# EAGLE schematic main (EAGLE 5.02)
CLASS: 5HNc; CREATE_DATE: 15.07.08; EDIT_DATE: 10.02.09; LAST_EDIT: 10.02; TITLE: xMedia - Connector; USERNAME: BWA; YEAR: 2009

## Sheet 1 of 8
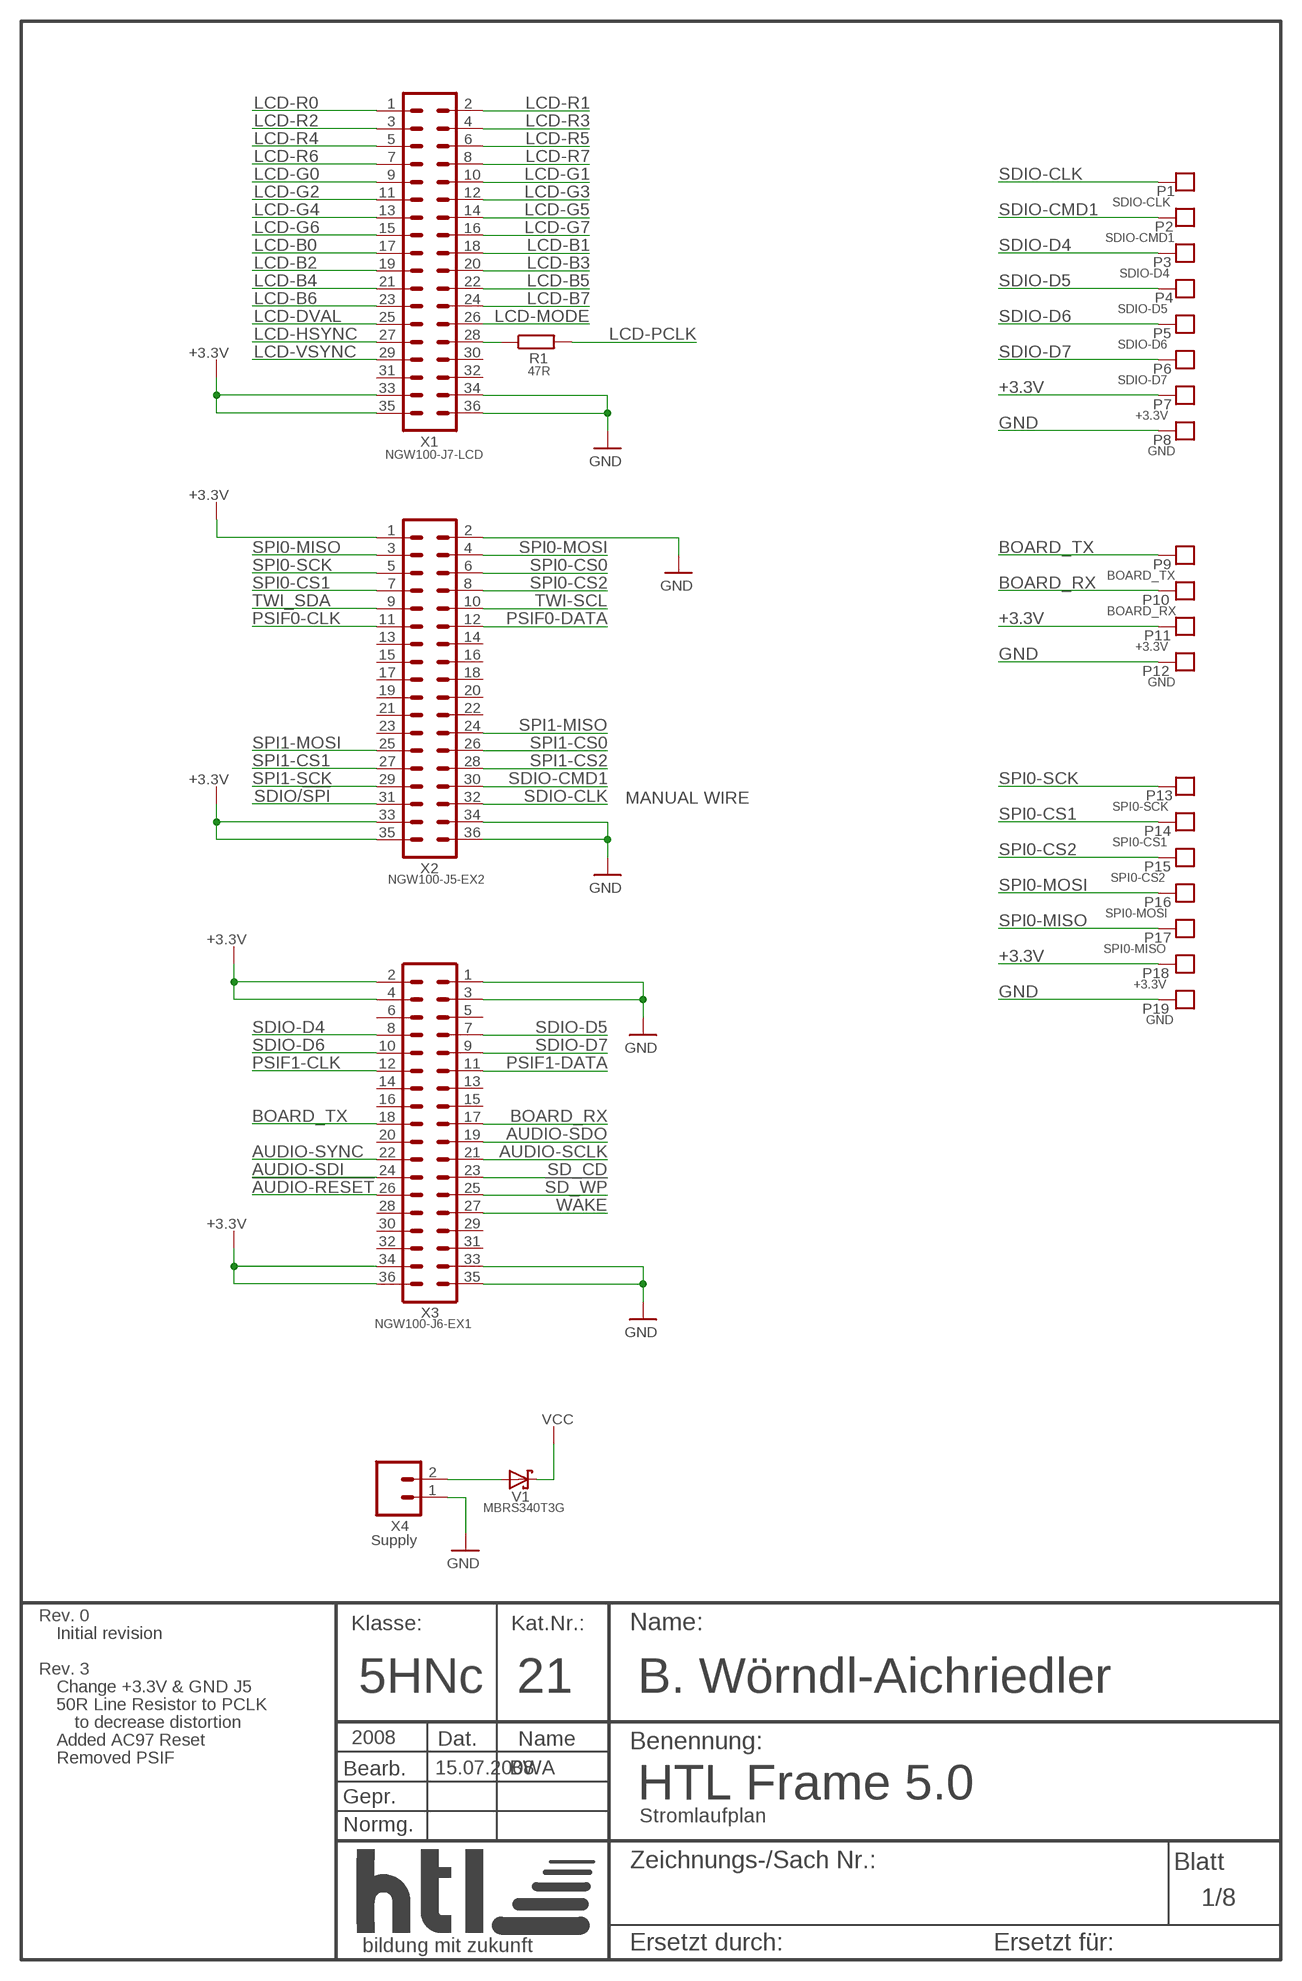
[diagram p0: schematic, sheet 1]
FRAME1 (HTL-FRAME-A4): CAT_NO: 21; CLASS: 5HNc; LAST_EDIT: 15.07.2008; SHORTNAME: BWA; SUBTITLE: Stromlaufplan; TITLE: HTL Frame 5.0; USERNAME: B. Wörndl-Aichriedler; YEAR: 2008

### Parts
P1  SDIO-CLK  TPB1,27  [B1,27]
P2  SDIO-CMD1  TPB1,27  [B1,27]
P3  SDIO-D4  TPB1,27  [B1,27]
P4  SDIO-D5  TPB1,27  [B1,27]
P5  SDIO-D6  TPB1,27  [B1,27]
P6  SDIO-D7  TPB1,27  [B1,27]
P7  +3.3V  TPB1,27  [B1,27]
P8  GND  TPB1,27  [B1,27]
P9  BOARD_TX  TPB1,27  [B1,27]
P10  BOARD_RX  TPB1,27  [B1,27]
P11  +3.3V  TPB1,27  [B1,27]
P12  GND  TPB1,27  [B1,27]
P13  SPI0-SCK  TPB1,27  [B1,27]
P14  SPI0-CS1  TPB1,27  [B1,27]
P15  SPI0-CS2  TPB1,27  [B1,27]
P16  SPI0-MOSI  TPB1,27  [B1,27]
P17  SPI0-MISO  TPB1,27  [B1,27]
P18  +3.3V  TPB1,27  [B1,27]
P19  GND  TPB1,27  [B1,27]
R1  47R  R-EU_R0805  [R0805]
V1  MBRS340T3G  SCHOTTKY-DIODESMC  [SMC]
X1  NGW100-J7-LCD  MA18-2WH  [MA18-2]
X2  NGW100-J5-EX2  MA18-2WH  [MA18-2]
X3  NGW100-J6-EX1  MA18-2WH  [MA18-2]
X4  Supply  M02  [02P]

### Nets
!AUDIO-RESET: X3.26 ; also sheet 6
!SD_WP: X3.25 ; also sheet 4
+3.3V: P7.PP(TP) P11.PP(TP) P18.PP(TP) X1.33 X1.35 X2.1 X2.33 X2.35 X3.2 X3.4 X3.34 X3.36 ; also sheet 2,3,4,5,6,7,8
AUDIO-SCLK: X3.21 ; also sheet 6
AUDIO-SDI: X3.24 ; also sheet 6
AUDIO-SDO: X3.19 ; also sheet 6
AUDIO-SYNC: X3.22 ; also sheet 6
BOARD_RX: P10.PP(TP) X3.17 ; also sheet 7
BOARD_TX: P9.PP(TP) X3.18 ; also sheet 7
GND: P8.PP(TP) P12.PP(TP) P19.PP(TP) X1.34 X1.36 X2.2 X2.34 X2.36 X3.1 X3.3 X3.33 X3.35 X4.1 ; also sheet 2,3,4,5,6,7,8
LCD-B0: X1.17 ; also sheet 2,3
LCD-B1: X1.18 ; also sheet 2,3
LCD-B2: X1.19 ; also sheet 2,3
LCD-B3: X1.20 ; also sheet 2,3
LCD-B4: X1.21 ; also sheet 2,3
LCD-B5: X1.22 ; also sheet 2,3
LCD-B6: X1.23 ; also sheet 2,3
LCD-B7: X1.24 ; also sheet 2,3
LCD-DVAL: X1.25 ; also sheet 3
LCD-G0: X1.9 ; also sheet 2,3
LCD-G1: X1.10 ; also sheet 2,3
LCD-G2: X1.11 ; also sheet 2,3
LCD-G3: X1.12 ; also sheet 2,3
LCD-G4: X1.13 ; also sheet 2,3
LCD-G5: X1.14 ; also sheet 2,3
LCD-G6: X1.15 ; also sheet 2,3
LCD-G7: X1.16 ; also sheet 2,3
LCD-HSYNC: X1.27 ; also sheet 2,3
LCD-MODE: X1.26
LCD-PCLK: R1.2 ; also sheet 2,3
LCD-R0: X1.1 ; also sheet 2,3
LCD-R1: X1.2 ; also sheet 2,3
LCD-R2: X1.3 ; also sheet 2,3
LCD-R3: X1.4 ; also sheet 2,3
LCD-R4: X1.5 ; also sheet 2,3
LCD-R5: X1.6 ; also sheet 2,3
LCD-R6: X1.7 ; also sheet 2,3
LCD-R7: X1.8 ; also sheet 2,3
LCD-VSYNC: X1.29 ; also sheet 2,3
N$15: V1.A X4.2
N$75: R1.1 X1.28
PSIF0-CLK: X2.11
PSIF0-DATA: X2.12
PSIF1-CLK: X3.12
PSIF1-DATA: X3.11
SD_CD: X3.23 ; also sheet 4
SDIO-CLK: P1.PP(TP) X2.32 ; also sheet 5
SDIO-CMD1: P2.PP(TP) X2.30 ; also sheet 5
SDIO-D4: P3.PP(TP) X3.8 ; also sheet 5
SDIO-D5: P4.PP(TP) X3.7 ; also sheet 5
SDIO-D6: P5.PP(TP) X3.10 ; also sheet 5
SDIO-D7: P6.PP(TP) X3.9 ; also sheet 5
SDIO/!SPI!: X2.31 ; also sheet 5
SPI0-CS0: X2.6
SPI0-CS1: P14.PP(TP) X2.7 ; also sheet 4
SPI0-CS2: P15.PP(TP) X2.8 ; also sheet 4
SPI0-MISO: P17.PP(TP) X2.3 ; also sheet 4
SPI0-MOSI: P16.PP(TP) X2.4 ; also sheet 4
SPI0-SCK: P13.PP(TP) X2.5 ; also sheet 4
SPI1-CS0: X2.26 ; also sheet 4
SPI1-CS1: X2.27
SPI1-CS2: X2.28
SPI1-MISO: X2.24 ; also sheet 4
SPI1-MOSI: X2.25 ; also sheet 4
SPI1-SCK: X2.29 ; also sheet 4
TWI-SCL: X2.10
TWI_SDA: X2.9
VCC: V1.C ; also sheet 2,6
WAKE: X3.27 ; also sheet 7
Unconnected: X1.30 X1.31 X1.32 X2.13 X2.14 X2.15 X2.16 X2.17 X2.18 X2.19 X2.20 X2.21 X2.22 X2.23 X3.5 X3.6 X3.13 X3.14 X3.15 X3.16 X3.20 X3.28 X3.29 X3.30 X3.31 X3.32

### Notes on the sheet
- MANUAL WIRE
- Rev. 0
- Initial revision
- Rev. 3
- Change +3.3V & GND J5
- 50R Line Resistor to PCLK
- to decrease distortion
- Added AC97 Reset
- Removed PSIF

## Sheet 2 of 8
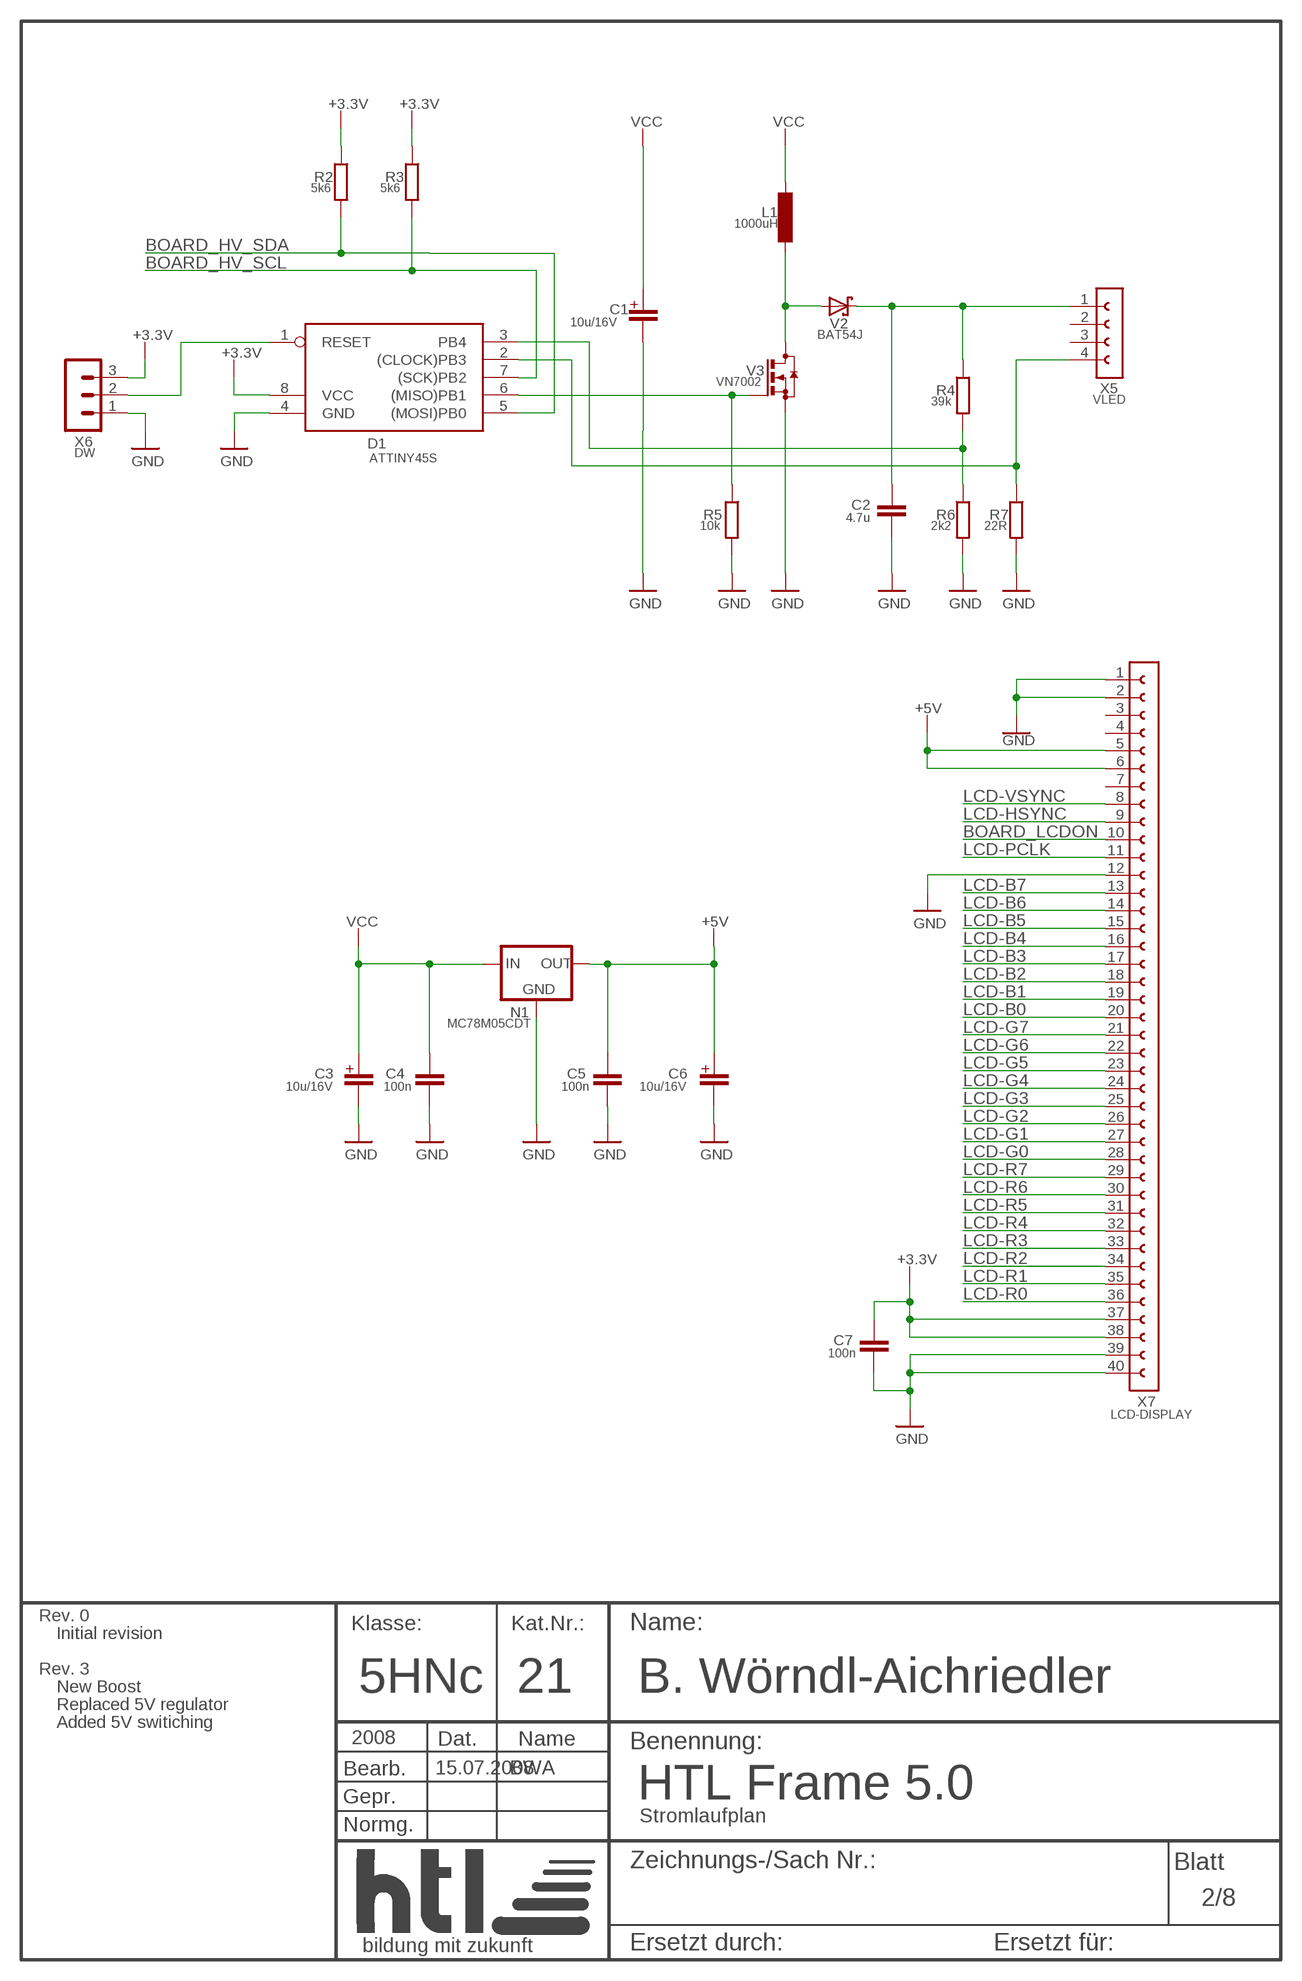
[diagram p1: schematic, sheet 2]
FRAME2 (HTL-FRAME-A4): CAT_NO: 21; CLASS: 5HNc; LAST_EDIT: 15.07.2008; SHORTNAME: BWA; SUBTITLE: Stromlaufplan; TITLE: HTL Frame 5.0; USERNAME: B. Wörndl-Aichriedler; YEAR: 2008

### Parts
C1  10u/16V  CPOL-EUB/3528-21W  [B/3528-21W]
C2  4.7u  C-EUC1206  [C1206]
C3  10u/16V  CPOL-EUB/3528-21W  [B/3528-21W]
C4  100n  C-EUC1206  [C1206]
C5  100n  C-EUC1206  [C1206]
C6  10u/16V  CPOL-EUB/3528-21W  [B/3528-21W]
C7  100n  C-EUC1206  [C1206]
D1  ATTINY45S  [SOIC8]
L1  1000uH  L-EU  [EPCOS10X10]
N1  MC78M05CDT  78  [DPAK]
R2  5k6  R-EU_R1206  [R1206]
R3  5k6  R-EU_R1206  [R1206]
R4  39k  R-EU_R0805  [R0805]
R5  10k  R-EU_R0805  [R0805]
R6  2k2  R-EU_R0805  [R0805]
R7  22R  R-EU_R1206  [R1206]
V2  BAT54J  SCHOTTKY-DIODE  [SOD323-W]
V3  VN7002  [SOT23]
X5  VLED  MOLEX4  [52745-0490]
X6  DW  MA03-1  [MA03-1]
X7  LCD-DISPLAY  ZIF-40  [ZIF40]

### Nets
+3.3V: C7.1 D1.8(VCC) R2.1 R3.1 X6.3 X7.37 X7.38 ; also sheet 1,3,4,5,6,7,8
+5V: C5.1 C6.+ N1.3(OUT) X7.5 X7.6
BOARD_HV_SCL: D1.7((SCK)PB2) R3.2 ; also sheet 7
BOARD_HV_SDA: D1.5((MOSI)PB0) R2.2 ; also sheet 7
BOARD_LCDON: X7.10 ; also sheet 7
GND: C1.- C2.2 C3.- C4.2 C5.2 C6.- C7.2 D1.4(GND) N1.4(GND) R5.2 R6.2 R7.2 V3.2(S) X6.1 X7.1 X7.2 X7.12 X7.39 X7.40 ; also sheet 1,3,4,5,6,7,8
LCD-B0: X7.20 ; also sheet 1,3
LCD-B1: X7.19 ; also sheet 1,3
LCD-B2: X7.18 ; also sheet 1,3
LCD-B3: X7.17 ; also sheet 1,3
LCD-B4: X7.16 ; also sheet 1,3
LCD-B5: X7.15 ; also sheet 1,3
LCD-B6: X7.14 ; also sheet 1,3
LCD-B7: X7.13 ; also sheet 1,3
LCD-G0: X7.28 ; also sheet 1,3
LCD-G1: X7.27 ; also sheet 1,3
LCD-G2: X7.26 ; also sheet 1,3
LCD-G3: X7.25 ; also sheet 1,3
LCD-G4: X7.24 ; also sheet 1,3
LCD-G5: X7.23 ; also sheet 1,3
LCD-G6: X7.22 ; also sheet 1,3
LCD-G7: X7.21 ; also sheet 1,3
LCD-HSYNC: X7.9 ; also sheet 1,3
LCD-PCLK: X7.11 ; also sheet 1,3
LCD-R0: X7.36 ; also sheet 1,3
LCD-R1: X7.35 ; also sheet 1,3
LCD-R2: X7.34 ; also sheet 1,3
LCD-R3: X7.33 ; also sheet 1,3
LCD-R4: X7.32 ; also sheet 1,3
LCD-R5: X7.31 ; also sheet 1,3
LCD-R6: X7.30 ; also sheet 1,3
LCD-R7: X7.29 ; also sheet 1,3
LCD-VSYNC: X7.8 ; also sheet 1,3
N$6: D1.6((MISO)PB1) R5.1 V3.1(G)
N$9: L1.P$2 V2.A V3.3(D)
N$10: D1.3(PB4) R4.2 R6.1
N$73: D1.1(RESET) X6.2
VCC: C1.+ C3.+ C4.1 L1.P$1 N1.1(IN) ; also sheet 1,6
VLED+: C2.1 R4.1 V2.C X5.1
VLED-: D1.2((CLOCK)PB3) R7.1 X5.4
Unconnected: X5.2 X5.3 X7.3 X7.4 X7.7

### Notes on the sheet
- Rev. 0
- Initial revision
- Rev. 3
- New Boost
- Replaced 5V regulator
- Added 5V switiching

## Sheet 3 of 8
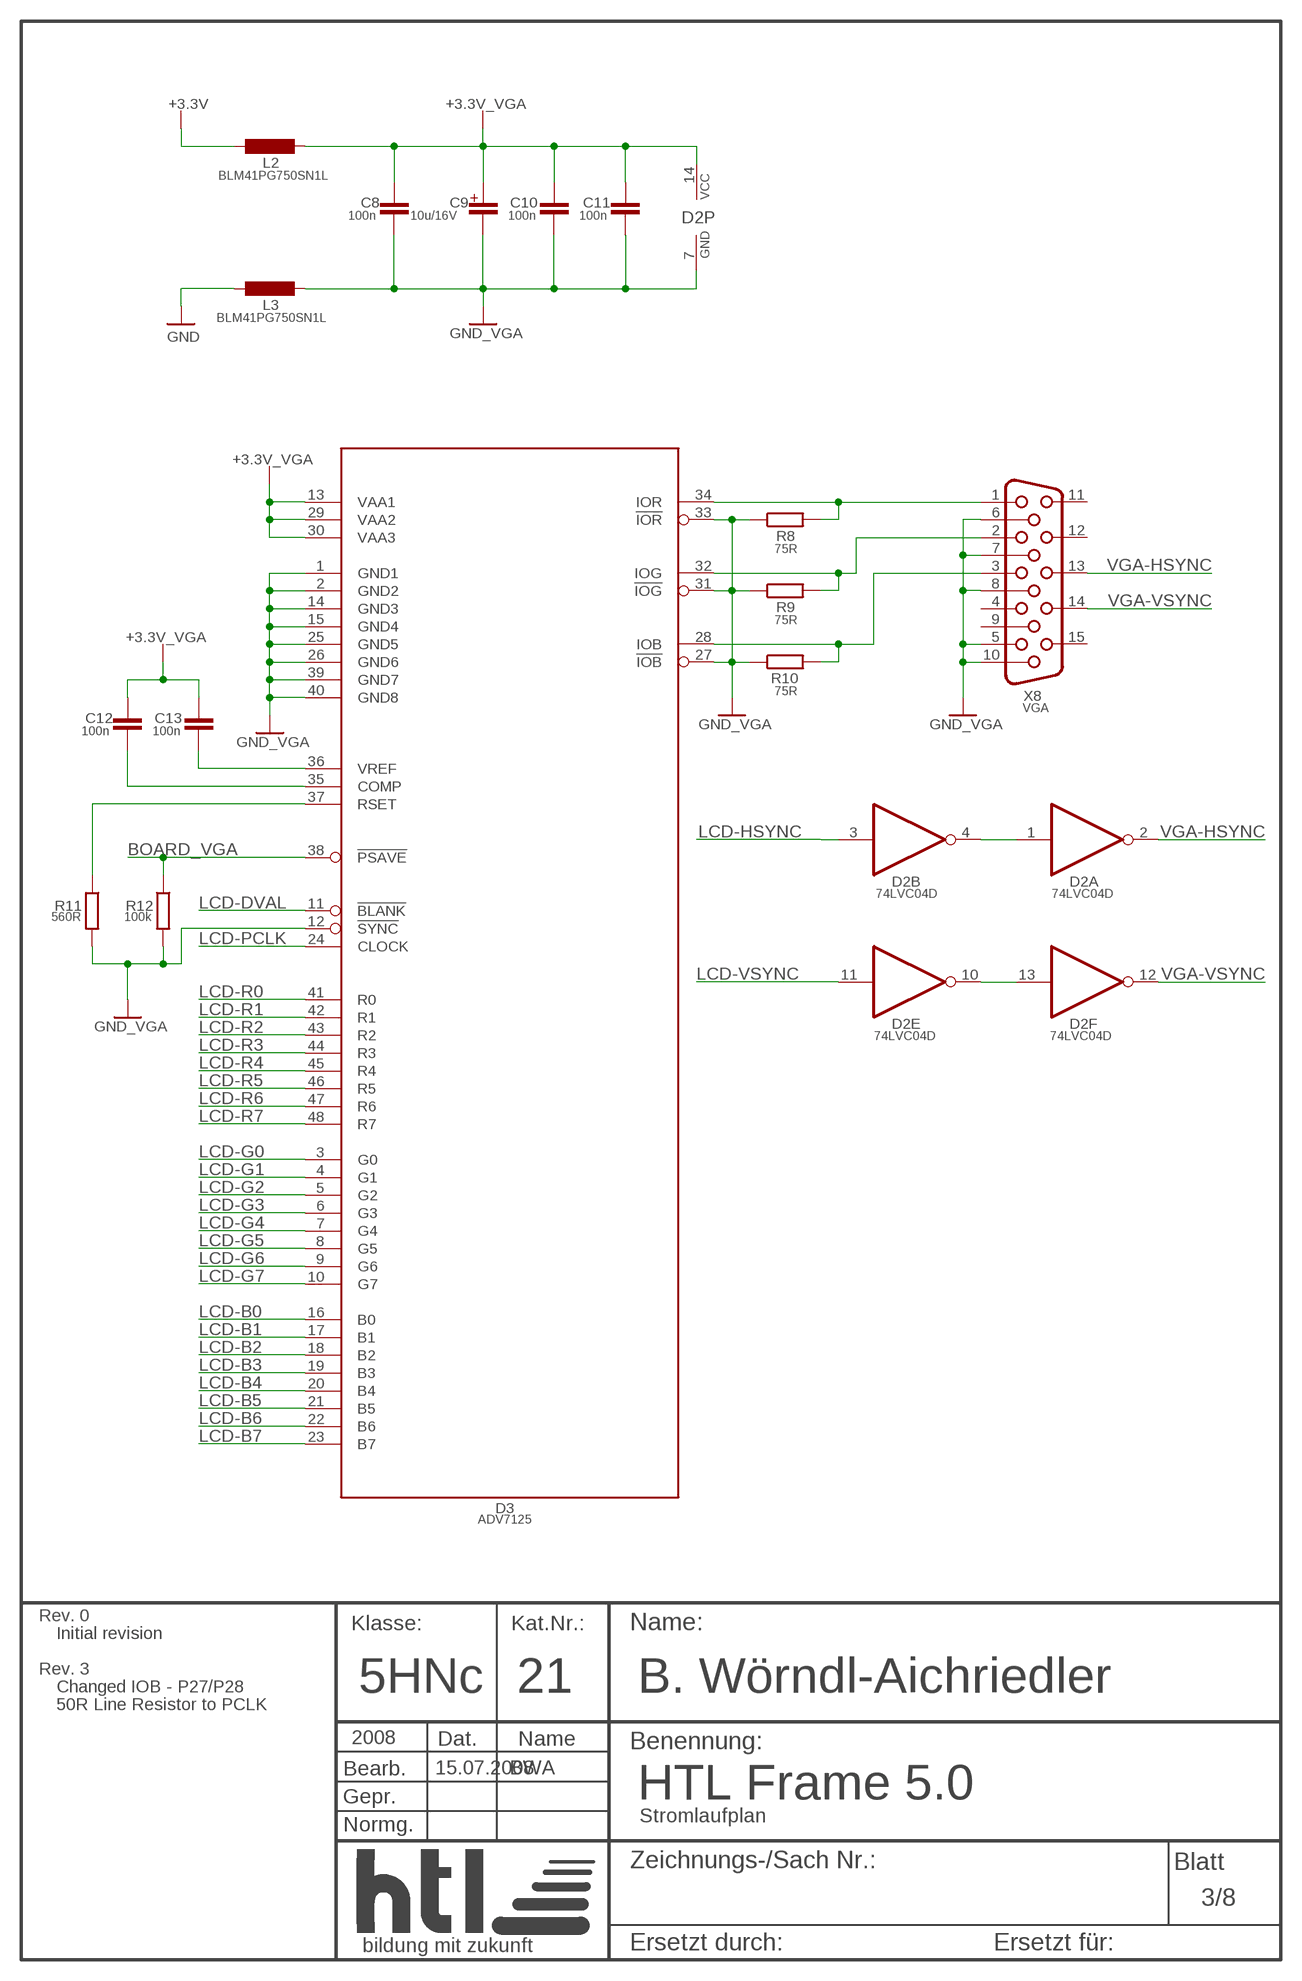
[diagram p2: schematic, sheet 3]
FRAME3 (HTL-FRAME-A4): CAT_NO: 21; CLASS: 5HNc; LAST_EDIT: 15.07.2008; SHORTNAME: BWA; SUBTITLE: Stromlaufplan; TITLE: HTL Frame 5.0; USERNAME: B. Wörndl-Aichriedler; YEAR: 2008

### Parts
C8  100n  C-EUC1206  [C1206]
C9  10u/16V  CPOL-EUB/3528-21W  [B/3528-21W]
C10  100n  C-EUC1206  [C1206]
C11  100n  C-EUC1206  [C1206]
C12  100n  C-EUC1206  [C1206]
C13  100n  C-EUC1206  [C1206]
D2  74LVC04D  [SO14]
D3  ADV7125  [TQFP48]
L2  BLM41PG750SN1L  L-EUL1812  [L1812]
L3  BLM41PG750SN1L  L-EUL1812  [L1812]
R8  75R  R-EU_R0805  [R0805]
R9  75R  R-EU_R0805  [R0805]
R10  75R  R-EU_R0805  [R0805]
R11  560R  R-EU_R0805  [R0805]
R12  100k  R-EU_R0805  [R0805]
X8  VGA  HF15H  [HDF15H]

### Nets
+3.3V: L2.1 ; also sheet 1,2,4,5,6,7,8
+3.3V_VGA: C8.1 C9.+ C10.1 C11.1 C12.1 C13.1 D2.14(P:VCC) D3.13(VAA1) D3.29(VAA2) D3.30(VAA3) L2.2
BOARD_VGA: D3.38(!PSAVE) R12.1 ; also sheet 7
GND: L3.1 ; also sheet 1,2,4,5,6,7,8
GND_VGA: C8.2 C9.- C10.2 C11.2 D2.7(P:GND) D3.1(GND1) D3.2(GND2) D3.12(!SYNC) D3.14(GND3) D3.15(GND4) D3.25(GND5) D3.26(GND6) D3.27(!IOB) D3.31(!IOG) D3.33(!IOR) D3.39(GND7) D3.40(GND8) L3.2 R8.1 R9.1 R10.1 R11.2 R12.2 X8.5 X8.6 X8.7 X8.8 X8.10
IOB: D3.28(IOB) R10.2 X8.3
IOG: D3.32(IOG) R9.2 X8.2
IOR: D3.34(IOR) R8.2 X8.1
LCD-B0: D3.16(B0) ; also sheet 1,2
LCD-B1: D3.17(B1) ; also sheet 1,2
LCD-B2: D3.18(B2) ; also sheet 1,2
LCD-B3: D3.19(B3) ; also sheet 1,2
LCD-B4: D3.20(B4) ; also sheet 1,2
LCD-B5: D3.21(B5) ; also sheet 1,2
LCD-B6: D3.22(B6) ; also sheet 1,2
LCD-B7: D3.23(B7) ; also sheet 1,2
LCD-DVAL: D3.11(!BLANK) ; also sheet 1
LCD-G0: D3.3(G0) ; also sheet 1,2
LCD-G1: D3.4(G1) ; also sheet 1,2
LCD-G2: D3.5(G2) ; also sheet 1,2
LCD-G3: D3.6(G3) ; also sheet 1,2
LCD-G4: D3.7(G4) ; also sheet 1,2
LCD-G5: D3.8(G5) ; also sheet 1,2
LCD-G6: D3.9(G6) ; also sheet 1,2
LCD-G7: D3.10(G7) ; also sheet 1,2
LCD-HSYNC: D2.3(B:I) ; also sheet 1,2
LCD-PCLK: D3.24(CLOCK) ; also sheet 1,2
LCD-R0: D3.41(R0) ; also sheet 1,2
LCD-R1: D3.42(R1) ; also sheet 1,2
LCD-R2: D3.43(R2) ; also sheet 1,2
LCD-R3: D3.44(R3) ; also sheet 1,2
LCD-R4: D3.45(R4) ; also sheet 1,2
LCD-R5: D3.46(R5) ; also sheet 1,2
LCD-R6: D3.47(R6) ; also sheet 1,2
LCD-R7: D3.48(R7) ; also sheet 1,2
LCD-VSYNC: D2.11(E:I) ; also sheet 1,2
N$1: D2.10(E:O) D2.13(F:I)
N$2: D2.1(A:I) D2.4(B:O)
N$7: C13.2 D3.36(VREF)
N$8: C12.2 D3.35(COMP)
N$11: D3.37(RSET) R11.1
VGA-HSYNC: D2.2(A:O) X8.13
VGA-VSYNC: D2.12(F:O) X8.14
Unconnected: D2.5(C:I) D2.6(C:O) D2.8(D:O) D2.9(D:I) X8.4 X8.9 X8.11 X8.12 X8.15

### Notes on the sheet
- Rev. 0
- Initial revision
- Rev. 3
- Changed IOB - P27/P28
- 50R Line Resistor to PCLK

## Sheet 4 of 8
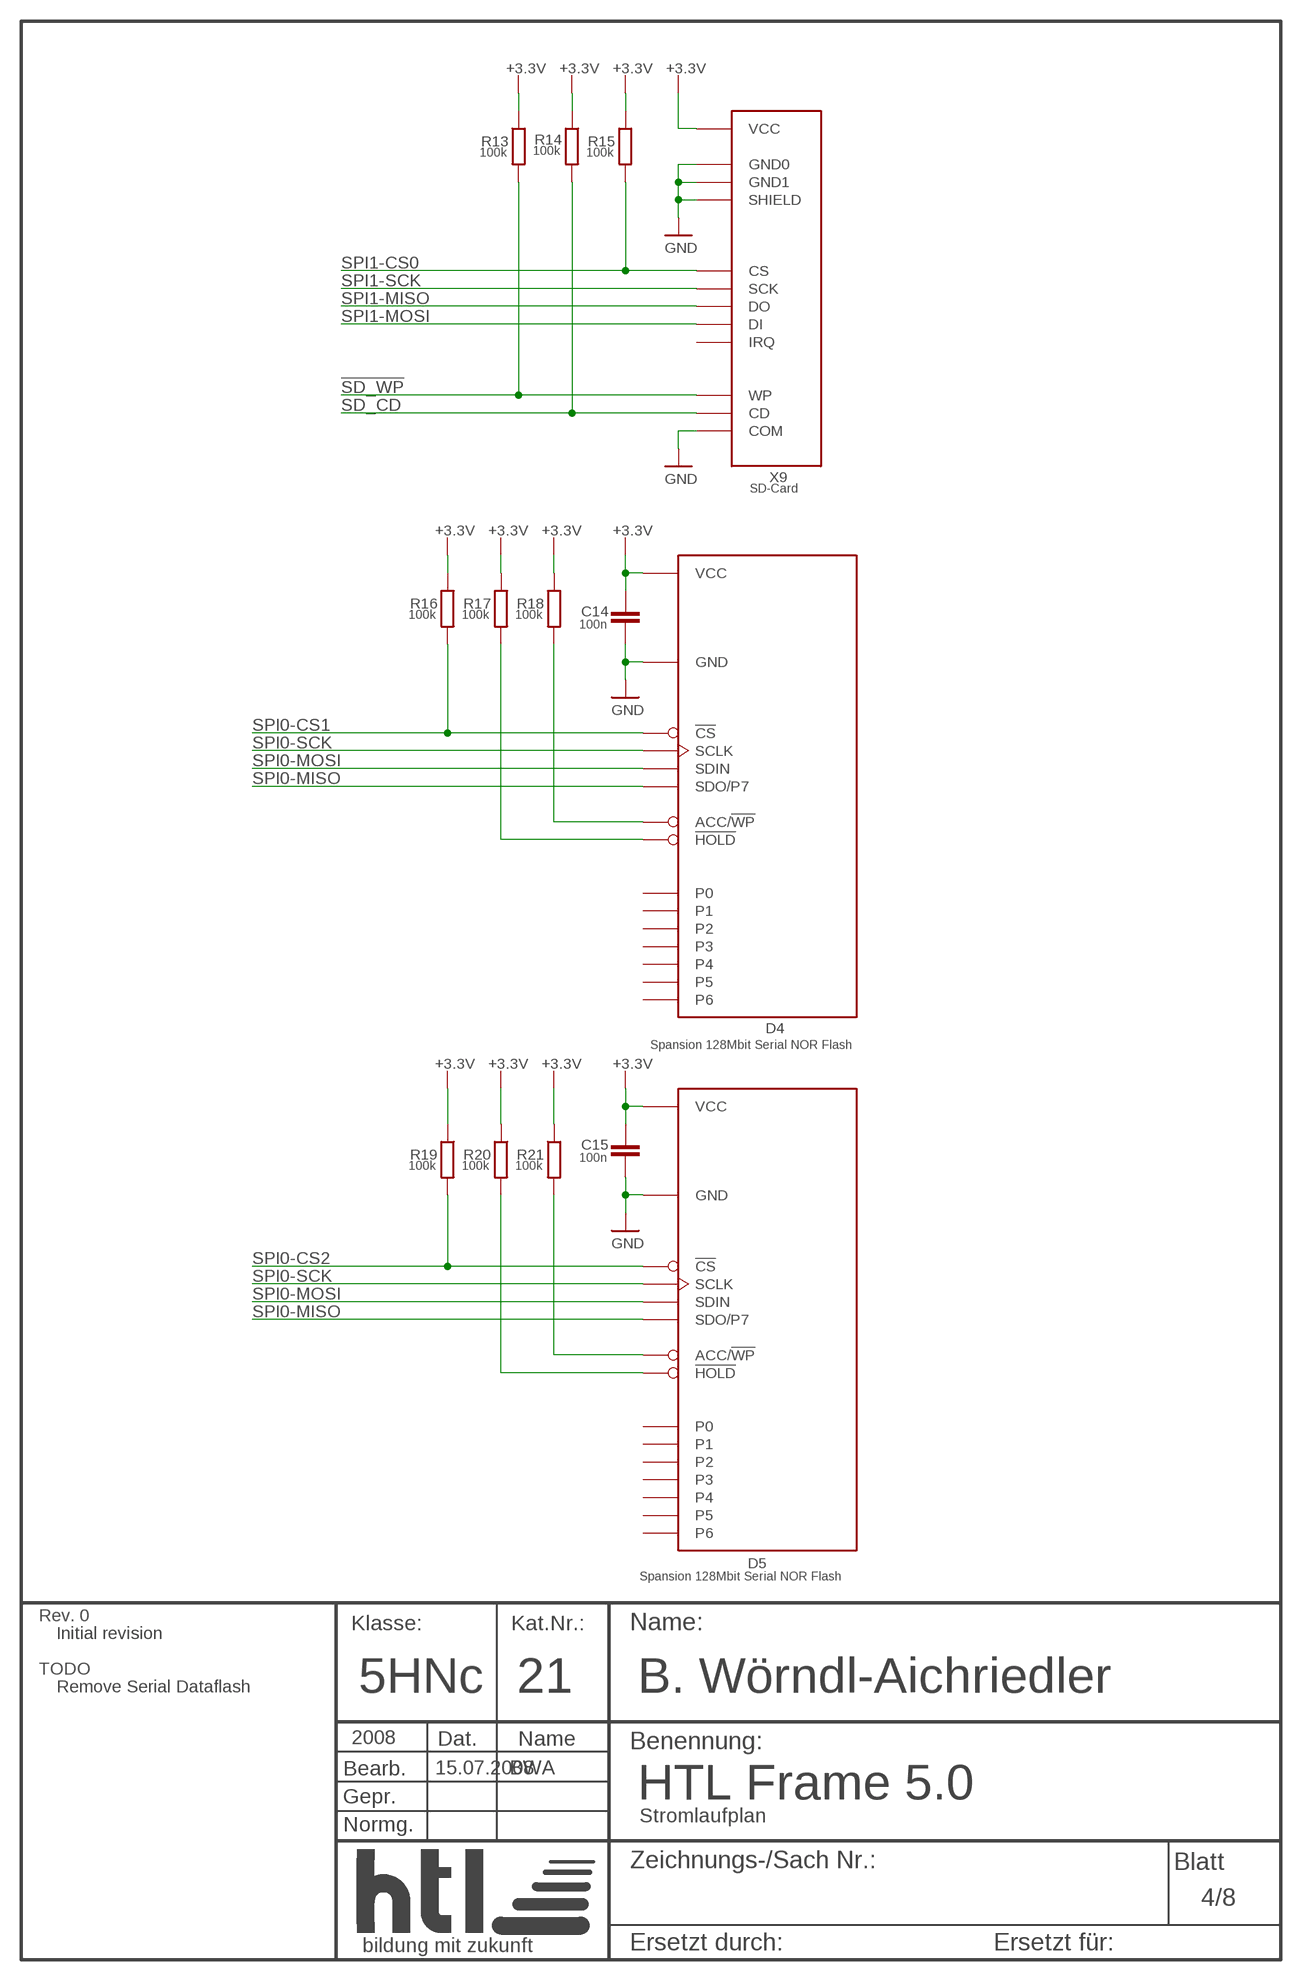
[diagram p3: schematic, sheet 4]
FRAME6 (HTL-FRAME-A4): CAT_NO: 21; CLASS: 5HNc; LAST_EDIT: 15.07.2008; SHORTNAME: BWA; SUBTITLE: Stromlaufplan; TITLE: HTL Frame 5.0; USERNAME: B. Wörndl-Aichriedler; YEAR: 2008

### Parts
C14  100n  C-EUC0805  [C0805]
C15  100n  C-EUC0805  [C0805]
D4  Spansion 128Mbit Serial NOR Flash  SPANSION_SPI_MEMORY  [SO16L]
D5  Spansion 128Mbit Serial NOR Flash  SPANSION_SPI_MEMORY  [SO16L]
R13  100k  R-EU_R0805  [R0805]
R14  100k  R-EU_R0805  [R0805]
R15  100k  R-EU_R0805  [R0805]
R16  100k  R-EU_R0805  [R0805]
R17  100k  R-EU_R0805  [R0805]
R18  100k  R-EU_R0805  [R0805]
R19  100k  R-EU_R0805  [R0805]
R20  100k  R-EU_R0805  [R0805]
R21  100k  R-EU_R0805  [R0805]
X9  SD-Card  SD_CARD_SOCKETSD  [SD-MMC_SOCKET-PP]

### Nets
!SD_WP: R13.2 X9.WP ; also sheet 1
+3.3V: C14.1 C15.1 D4.2(VCC) D5.2(VCC) R13.1 R14.1 R15.1 R16.1 R17.1 R18.1 R19.1 R20.1 R21.1 X9.4(VCC) ; also sheet 1,2,3,5,6,7,8
GND: C14.2 C15.2 D4.10(GND) D5.10(GND) X9.3(GND0) X9.6(GND1) X9.14(SHIELD) X9.SW(COM) ; also sheet 1,2,3,5,6,7,8
N$5: D5.9(ACC/!WP!) R21.2
N$63: D5.1(!HOLD) R20.2
N$68: D4.9(ACC/!WP!) R18.2
N$69: D4.1(!HOLD) R17.2
SD_CD: R14.2 X9.CD ; also sheet 1
SPI0-CS1: D4.7(!CS) R16.2 ; also sheet 1
SPI0-CS2: D5.7(!CS) R19.2 ; also sheet 1
SPI0-MISO: D4.8(SDO/P7) D5.8(SDO/P7) ; also sheet 1
SPI0-MOSI: D4.15(SDIN) D5.15(SDIN) ; also sheet 1
SPI0-SCK: D4.16(SCLK) D5.16(SCLK) ; also sheet 1
SPI1-CS0: R15.2 X9.1(CS) ; also sheet 1
SPI1-MISO: X9.7(DO) ; also sheet 1
SPI1-MOSI: X9.2(DI) ; also sheet 1
SPI1-SCK: X9.5(SCK) ; also sheet 1
Unconnected: D4.4(P2) D4.5(P1) D4.6(P0) D4.11(P3) D4.12(P4) D4.13(P5) D4.14(P6) D5.4(P2) D5.5(P1) D5.6(P0) D5.11(P3) D5.12(P4) D5.13(P5) D5.14(P6) X9.8(IRQ)

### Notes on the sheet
- Rev. 0
- Initial revision
- TODO
- Remove Serial Dataflash

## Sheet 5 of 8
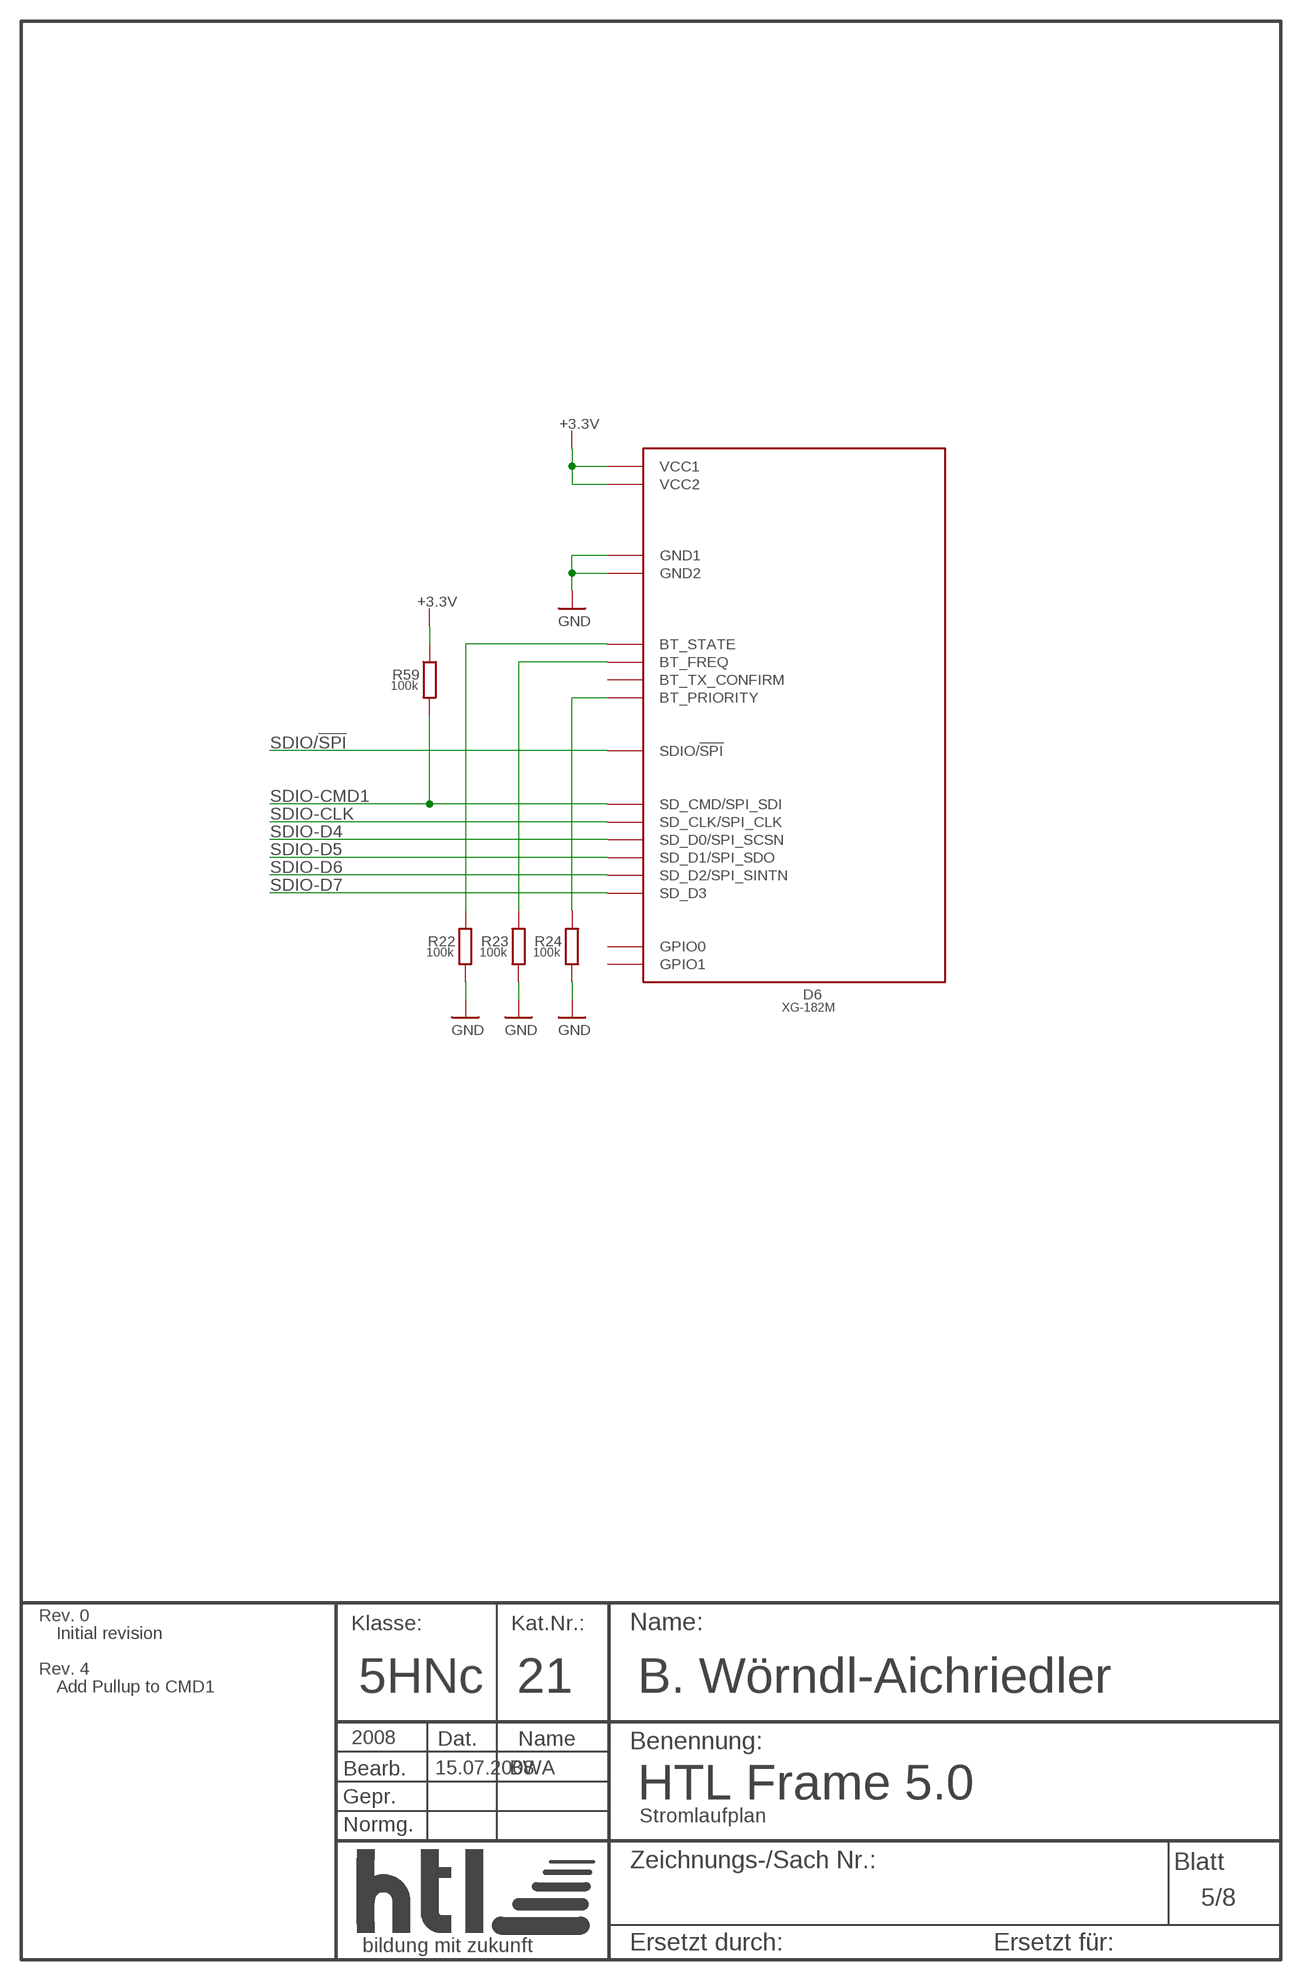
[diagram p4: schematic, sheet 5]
FRAME5 (HTL-FRAME-A4): CAT_NO: 21; CLASS: 5HNc; LAST_EDIT: 15.07.2008; SHORTNAME: BWA; SUBTITLE: Stromlaufplan; TITLE: HTL Frame 5.0; USERNAME: B. Wörndl-Aichriedler; YEAR: 2008

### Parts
D6  XG-182M  [XG-182M]
R22  100k  R-EU_R0805  [R0805]
R23  100k  R-EU_R0805  [R0805]
R24  100k  R-EU_R0805  [R0805]
R59  100k  R-EU_R0805  [R0805]

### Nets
+3.3V: D6.P$13(VCC1) D6.P$38(VCC2) R59.1 ; also sheet 1,2,3,4,6,7,8
GND: D6.P$1(GND1) D6.P$50(GND2) R22.2 R23.2 R24.2 ; also sheet 1,2,3,4,6,7,8
N$70: D6.P$2(BT_STATE) R22.1
N$71: D6.P$5(BT_PRIORITY) R24.1
N$72: D6.P$3(BT_FREQ) R23.1
SDIO-CLK: D6.P$32(SD_CLK/SPI_CLK) ; also sheet 1
SDIO-CMD1: D6.P$9(SD_CMD/SPI_SDI) R59.2 ; also sheet 1
SDIO-D4: D6.P$25(SD_D0/SPI_SCSN) ; also sheet 1
SDIO-D5: D6.P$34(SD_D1/SPI_SDO) ; also sheet 1
SDIO-D6: D6.P$10(SD_D2/SPI_SINTN) ; also sheet 1
SDIO-D7: D6.P$35(SD_D3) ; also sheet 1
SDIO/!SPI!: D6.P$49(SDIO/!SPI) ; also sheet 1
Unconnected: D6.P$4(BT_TX_CONFIRM) D6.P$39(GPIO0) D6.P$46(GPIO1)

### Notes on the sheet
- Rev. 0
- Initial revision
- Rev. 4
- Add Pullup to CMD1

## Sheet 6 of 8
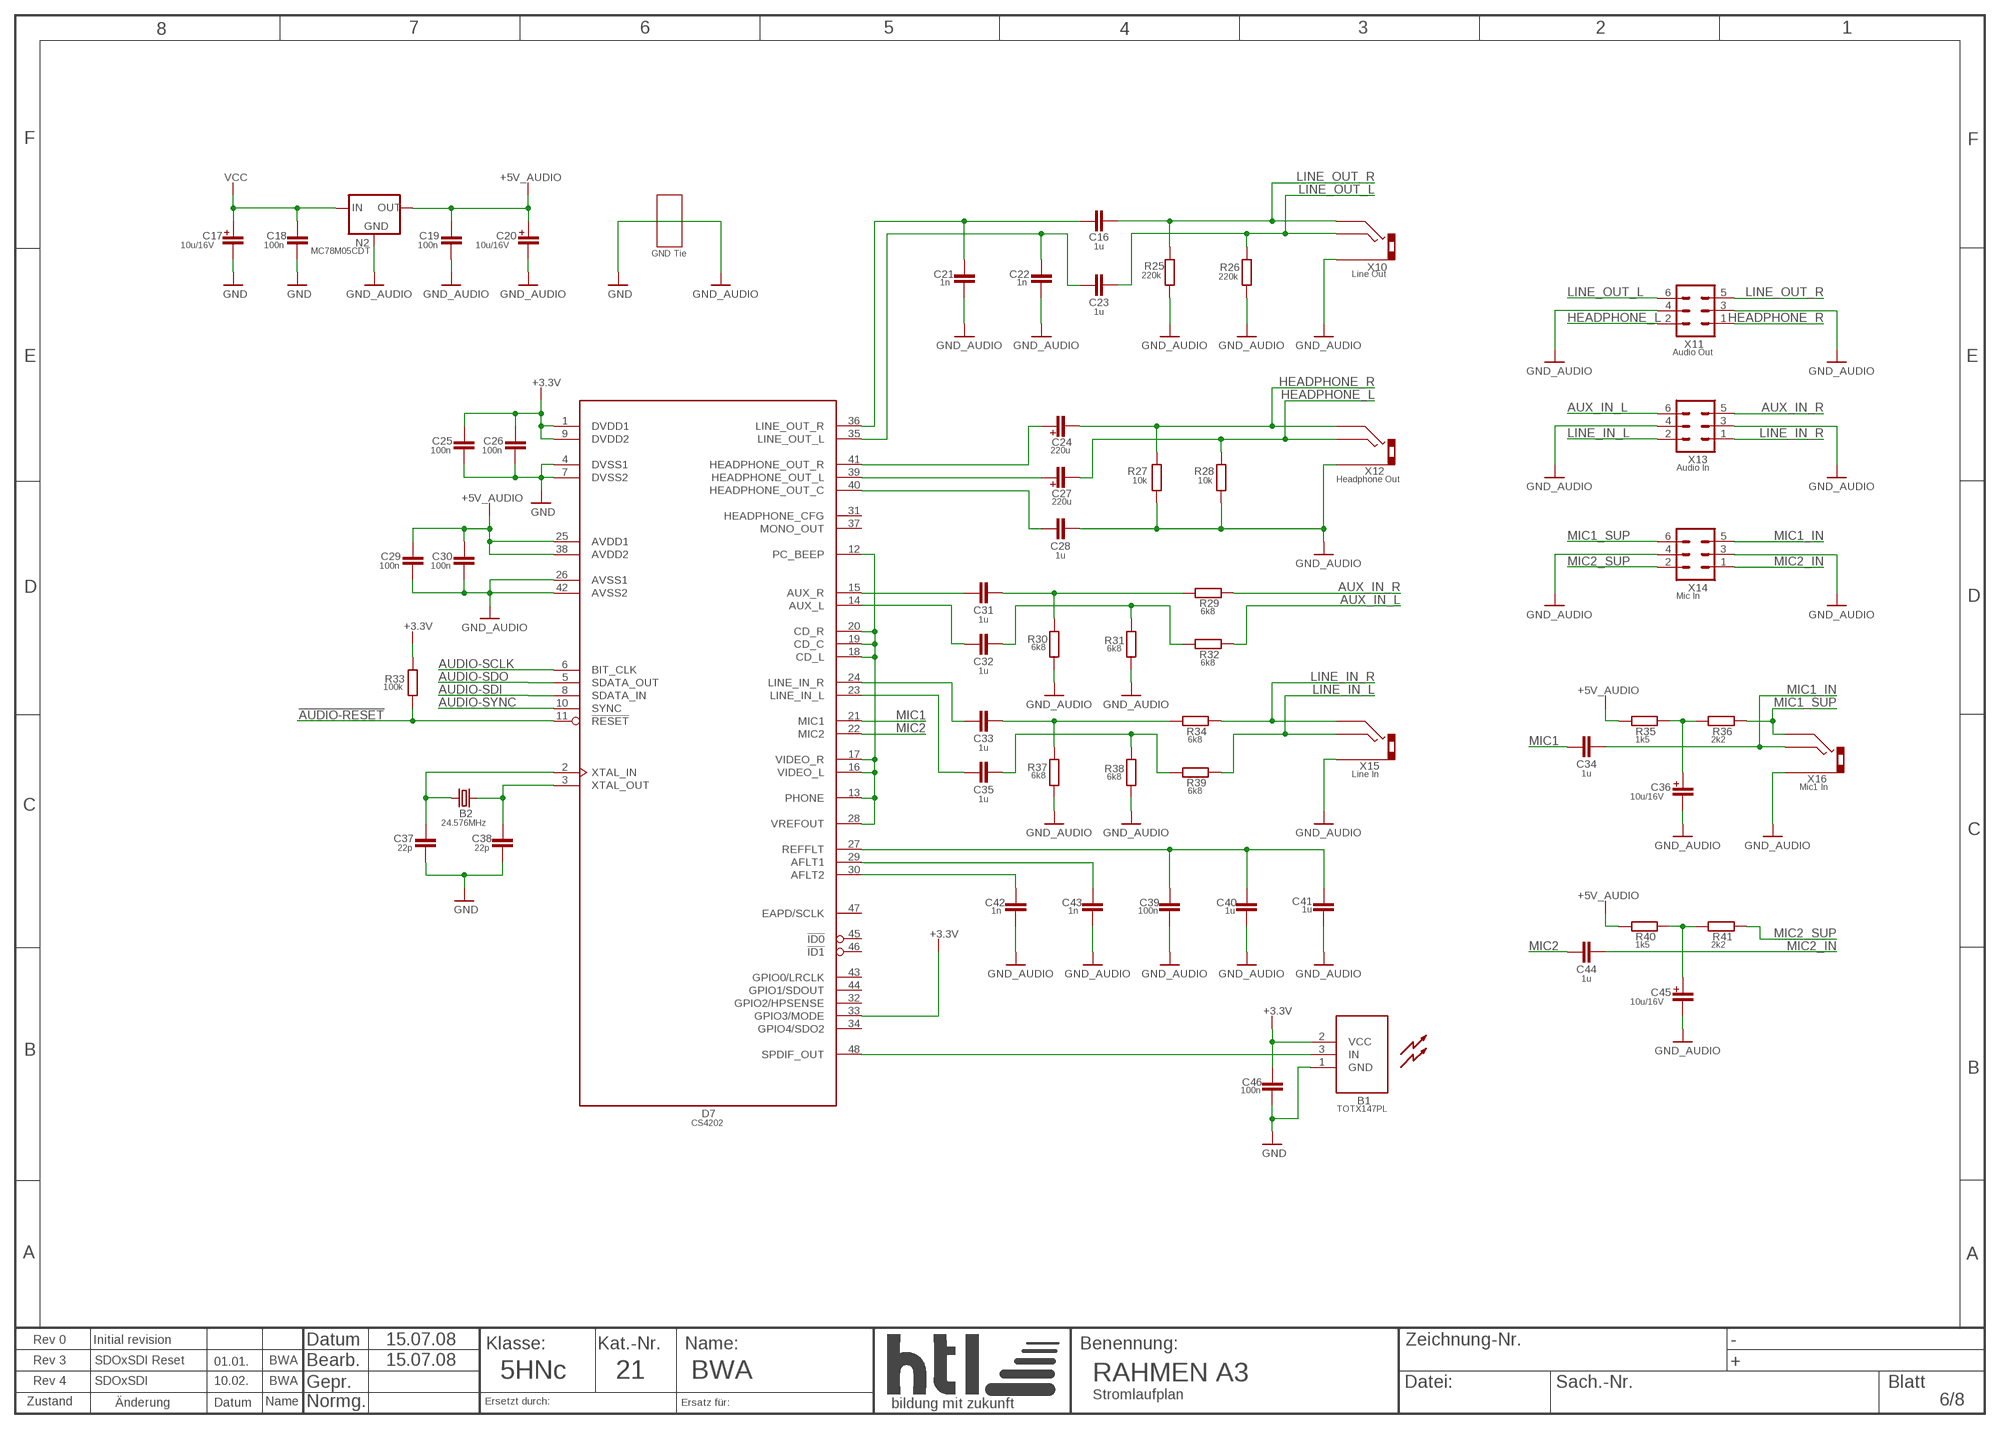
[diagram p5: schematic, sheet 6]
FRAME4 (HTL-FRAME-A3): CAT_NO: 21; CLASS: 5HNc; CREATE_DATE: 15.07.08; EDIT_DATE: 15.07.08; SUBTITLE: Stromlaufplan; TITLE: RAHMEN A3; USERNAME: BWA

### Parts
B1  TOTX147PL  [TOTX147PL]
B2  24.576MHz  CRYSTALSM49  [SM49]
C16  1u  C-EUC0805  [C0805]
C17  10u/16V  CPOL-EUB/3528-21W  [B/3528-21W]
C18  100n  C-EUC1206  [C1206]
C19  100n  C-EUC1206  [C1206]
C20  10u/16V  CPOL-EUB/3528-21W  [B/3528-21W]
C21  1n  C-EUC0805  [C0805]
C22  1n  C-EUC0805  [C0805]
C23  1u  C-EUC0805  [C0805]
C24  220u  CPOL-EUE  [PANASONIC_E]
C25  100n  C-EUC1206  [C1206]
C26  100n  C-EUC1206  [C1206]
C27  220u  CPOL-EUE  [PANASONIC_E]
C28  1u  C-EUC0805  [C0805]
C29  100n  C-EUC0805  [C0805]
C30  100n  C-EUC0805  [C0805]
C31  1u  C-EUC0805  [C0805]
C32  1u  C-EUC0805  [C0805]
C33  1u  C-EUC0805  [C0805]
C34  1u  C-EUC0805  [C0805]
C35  1u  C-EUC0805  [C0805]
C36  10u/16V  CPOL-EUB/3528-21W  [B/3528-21W]
C37  22p  C-EUC0805  [C0805]
C38  22p  C-EUC0805  [C0805]
C39  100n  C-EUC0805  [C0805]
C40  1u  C-EUC0805  [C0805]
C41  1u  C-EUC0805  [C0805]
C42  1n  C-EUC0805  [C0805]
C43  1n  C-EUC0805  [C0805]
C44  1u  C-EUC0805  [C0805]
C45  10u/16V  CPOL-EUB/3528-21W  [B/3528-21W]
C46  100n  C-EUC0805  [C0805]
D7  CS4202  [TQFP48]
N2  MC78M05CDT  78  [DPAK]
R25  220k  R-EU_R0805  [R0805]
R26  220k  R-EU_R0805  [R0805]
R27  10k  R-EU_R0805  [R0805]
R28  10k  R-EU_R0805  [R0805]
R29  6k8  R-EU_R0805  [R0805]
R30  6k8  R-EU_R0805  [R0805]
R31  6k8  R-EU_R0805  [R0805]
R32  6k8  R-EU_R0805  [R0805]
R33  100k  R-EU_R0805  [R0805]
R34  6k8  R-EU_R0805  [R0805]
R35  1k5  R-EU_R0805  [R0805]
R36  2k2  R-EU_R0805  [R0805]
R37  6k8  R-EU_R0805  [R0805]
R38  6k8  R-EU_R0805  [R0805]
R39  6k8  R-EU_R0805  [R0805]
R40  1k5  R-EU_R0805  [R0805]
R41  2k2  R-EU_R0805  [R0805]
X10  Line Out  1503_03  [1503_03]
X11  Audio Out  MA03-2  [MA03-2]
X12  Headphone Out  1503_03  [1503_03]
X13  Audio In  MA03-2  [MA03-2]
X14  Mic In  MA03-2  [MA03-2]
X15  Line In  1503_03  [1503_03]
X16  Mic1 In  1503_03  [1503_03]

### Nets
!AUDIO-RESET: D7.11(!RESET) R33.2 ; also sheet 1
+3.3V: B1.2(VCC) C25.1 C26.1 C46.1 D7.1(DVDD1) D7.9(DVDD2) D7.33(GPIO3/MODE) R33.1 ; also sheet 1,2,3,4,5,7,8
+5V_AUDIO: C19.1 C20.+ C29.1 C30.1 D7.25(AVDD1) D7.38(AVDD2) N2.3(OUT) R35.2 R40.2
AUDIO-SCLK: D7.6(BIT_CLK) ; also sheet 1
AUDIO-SDI: D7.8(SDATA_IN) ; also sheet 1
AUDIO-SDO: D7.5(SDATA_OUT) ; also sheet 1
AUDIO-SYNC: D7.10(SYNC) ; also sheet 1
AUX_IN_L: R32.2 X13.6
AUX_IN_R: R29.2 X13.5
GND: B1.1(GND) C17.- C18.2 C19.2 C20.- C21.1 C22.1 C25.2 C26.2 C28.2 C29.2 C30.2 C36.- C37.2 C38.2 C39.2 C40.2 C41.2 C42.1 C43.1 C45.- C46.2 D7.4(DVSS1) D7.7(DVSS2) D7.26(AVSS1) D7.42(AVSS2) N2.4(GND) R25.1 R26.1 R27.1 R28.1 R30.2 R31.2 R37.2 R38.2 X10.GND X11.3 X11.4 X12.GND X13.3 X13.4 X14.3 X14.4 X15.GND X16.GND ; supply symbol labelled GND_AUDIO ; also sheet 1,2,3,4,5,7,8
HEADPHONE_L: C27.- R28.2 X11.2 X12.L
HEADPHONE_R: C24.- R27.2 X11.1 X12.R
LINE_IN_L: R39.2 X13.2 X15.L
LINE_IN_R: R34.2 X13.1 X15.R
LINE_OUT_L: C23.2 R26.2 X10.L X11.6
LINE_OUT_R: C16.2 R25.2 X10.R X11.5
MIC1: C34.1 D7.21(MIC1)
MIC1_IN: C34.2 X14.5 X16.L
MIC1_SUP: R36.1 X14.6 X16.R
MIC2: C44.1 D7.22(MIC2)
MIC2_IN: C44.2 X14.1
MIC2_SUP: R41.1 X14.2
N$12: B2.2 C38.1 D7.3(XTAL_OUT)
N$13: B2.1 C37.1 D7.2(XTAL_IN)
N$16: C32.2 R31.1 R32.1
N$17: C31.2 R29.1 R30.1
N$18: C16.1 C21.2 D7.36(LINE_OUT_R)
N$19: C22.2 C23.1 D7.35(LINE_OUT_L)
N$20: C24.+ D7.41(HEADPHONE_OUT_R)
N$21: C27.+ D7.39(HEADPHONE_OUT_L)
N$22: D7.12(PC_BEEP) D7.13(PHONE) D7.16(VIDEO_L) D7.17(VIDEO_R) D7.18(CD_L) D7.19(CD_C) D7.20(CD_R) D7.28(VREFOUT)
N$23: C31.1 D7.15(AUX_R)
N$24: C28.1 D7.40(HEADPHONE_OUT_C)
N$25: C32.1 D7.14(AUX_L)
N$26: C45.+ R40.1 R41.2
N$27: C35.2 R38.1 R39.1
N$28: C33.2 R34.1 R37.1
N$29: C36.+ R35.1 R36.2
N$30: C33.1 D7.24(LINE_IN_R)
N$31: C35.1 D7.23(LINE_IN_L)
N$32: C39.1 C40.1 C41.1 D7.27(REFFLT)
N$33: C42.2 D7.30(AFLT2)
N$34: C43.2 D7.29(AFLT1)
N$35: B1.3(IN) D7.48(SPDIF_OUT)
VCC: C17.+ C18.1 N2.1(IN) ; also sheet 1,2
Unconnected: D7.31(HEADPHONE_CFG) D7.32(GPIO2/HPSENSE) D7.34(GPIO4/SDO2) D7.37(MONO_OUT) D7.43(GPIO0/LRCLK) D7.44(GPIO1/SDOUT) D7.45(!ID0) D7.46(!ID1) D7.47(EAPD/SCLK)

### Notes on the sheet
- GND Tie
- Rev 0 | Initial revision
- Rev 3 | SDOxSDI Reset | 01.01. | BWA
- Rev 4 | SDOxSDI | 10.02. | BWA

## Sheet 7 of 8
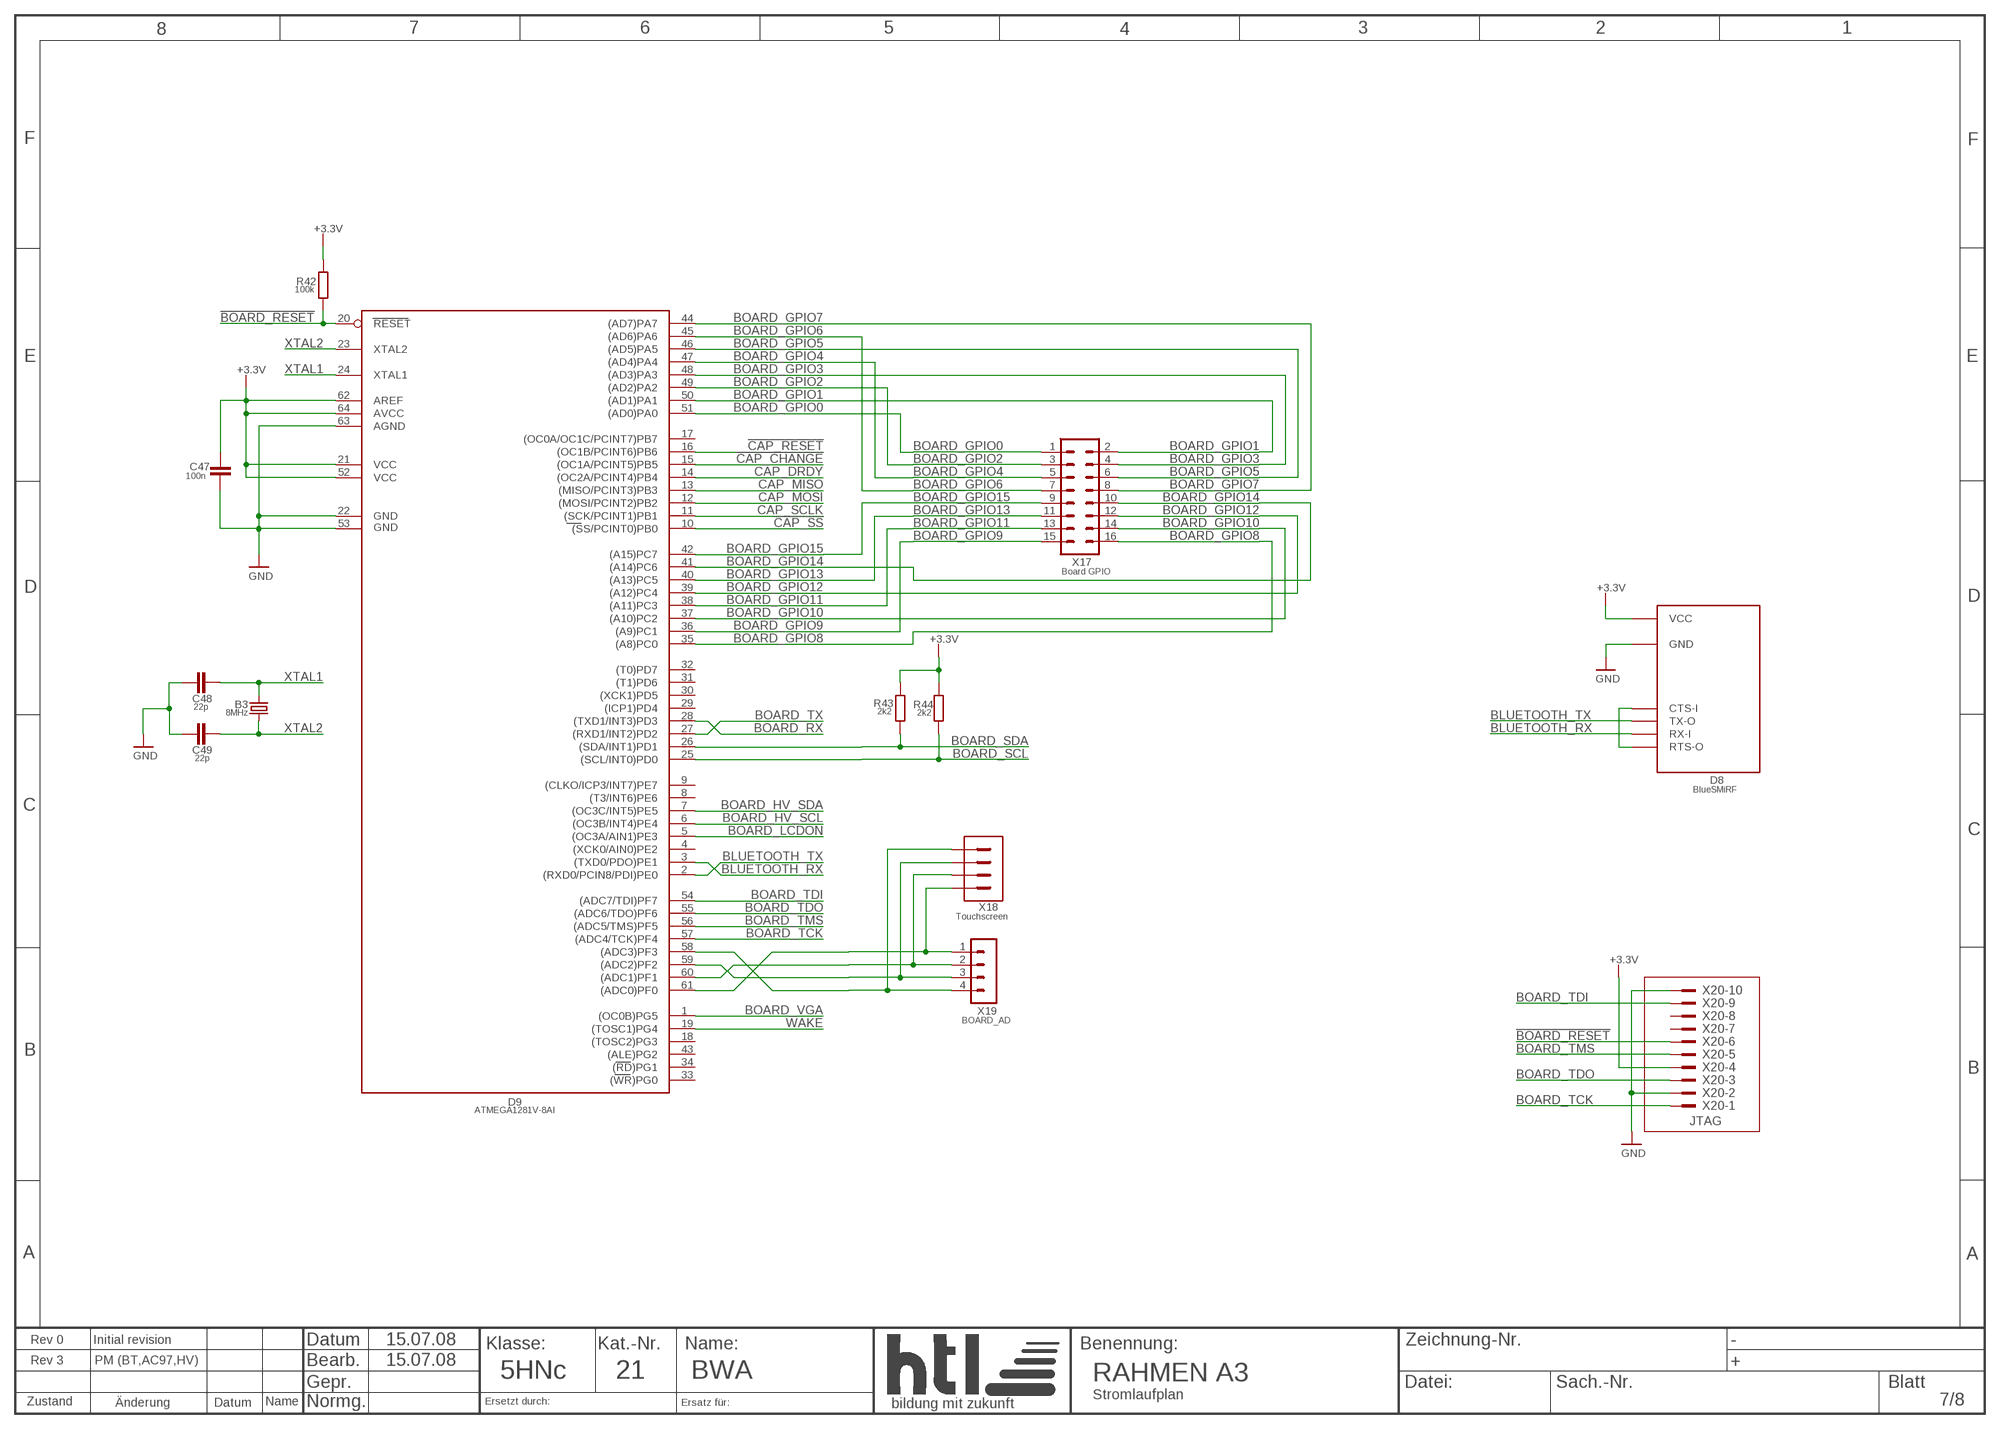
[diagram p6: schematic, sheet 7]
U$1 (HTL-FRAME-A3): CAT_NO: 21; CLASS: 5HNc; CREATE_DATE: 15.07.08; EDIT_DATE: 15.07.08; SUBTITLE: Stromlaufplan; TITLE: RAHMEN A3; USERNAME: BWA

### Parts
B3  8MHz  CRYSTALHC49UP  [HC49UP]
C47  100n  C-EUC1206  [C1206]
C48  22p  C-EUC0805  [C0805]
C49  22p  C-EUC0805  [C0805]
D8  BlueSMiRF  BLUE_SMIRF  [BLUE_SMIRF_SOCKET]
D9  ATMEGA1281V-8AI  ATMEGA2561V-8AI  [TQFP64]
R42  100k  R-EU_R0805  [R0805]
R43  2k2  R-EU_R0805  [R0805]
R44  2k2  R-EU_R0805  [R0805]
X17  Board GPIO  MA08-2  [MA08-2]
X18  Touchscreen  FPC-4  [FPC-4-1MM]
X19  BOARD_AD  MA04-1  [MA04-1]
X20  JTAG  2510-  [PAK100/2500-10]

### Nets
!BOARD_RESET: D9.20(RESET) R42.2 X20.6
!CAP_CHANGE: D9.15((OC1A/PCINT5)PB5) ; also sheet 8
!CAP_RESET: D9.16((OC1B/PCINT6)PB6) ; also sheet 8
!CAP_SS: D9.10((SS/PCINT0)PB0) ; also sheet 8
+3.3V: C47.1 D8.PWR(VCC) D9.21(VCC) D9.52(VCC1) D9.62(AREF) D9.64(AVCC) R42.1 R43.2 R44.2 X20.4 ; also sheet 1,2,3,4,5,6,8
BLUETOOTH_RX: D8.RX(RX-I) D9.3((TXD0/PDO)PE1)
BLUETOOTH_TX: D8.TX(TX-O) D9.2((RXD0/PCIN8/PDI)PE0)
BOARD_GPAD0: D9.61((ADC0)PF0) X18.P$4 X19.1
BOARD_GPAD1: D9.60((ADC1)PF1) X18.P$3 X19.2
BOARD_GPAD2: D9.59((ADC2)PF2) X18.P$2 X19.3
BOARD_GPAD3: D9.58((ADC3)PF3) X18.P$1 X19.4
BOARD_GPIO0: D9.51((AD0)PA0) X17.1
BOARD_GPIO1: D9.50((AD1)PA1) X17.2
BOARD_GPIO2: D9.49((AD2)PA2) X17.3
BOARD_GPIO3: D9.48((AD3)PA3) X17.4
BOARD_GPIO4: D9.47((AD4)PA4) X17.5
BOARD_GPIO5: D9.46((AD5)PA5) X17.6
BOARD_GPIO6: D9.45((AD6)PA6) X17.7
BOARD_GPIO7: D9.44((AD7)PA7) X17.8
BOARD_GPIO8: D9.35((A8)PC0) X17.16
BOARD_GPIO9: D9.36((A9)PC1) X17.15
BOARD_GPIO10: D9.37((A10)PC2) X17.14
BOARD_GPIO11: D9.38((A11)PC3) X17.13
BOARD_GPIO12: D9.39((A12)PC4) X17.12
BOARD_GPIO13: D9.40((A13)PC5) X17.11
BOARD_GPIO14: D9.41((A14)PC6) X17.10
BOARD_GPIO15: D9.42((A15)PC7) X17.9
BOARD_HV_SCL: D9.6((OC3B/INT4)PE4) ; also sheet 2
BOARD_HV_SDA: D9.7((OC3C/INT5)PE5) ; also sheet 2
BOARD_LCDON: D9.5((OC3A/AIN1)PE3) ; also sheet 2
BOARD_RX: D9.28((TXD1/INT3)PD3) ; also sheet 1
BOARD_SCL: D9.25((SCL/INT0)PD0) R44.1 ; also sheet 8
BOARD_SDA: D9.26((SDA/INT1)PD1) R43.1 ; also sheet 8
BOARD_TCK: D9.57((ADC4/TCK)PF4) X20.1
BOARD_TDI: D9.54((ADC7/TDI)PF7) X20.9
BOARD_TDO: D9.55((ADC6/TDO)PF6) X20.3
BOARD_TMS: D9.56((ADC5/TMS)PF5) X20.5
BOARD_TX: D9.27((RXD1/INT2)PD2) ; also sheet 1
BOARD_VGA: D9.1((OC0B)PG5) ; also sheet 3
CAP_DRDY: D9.14((OC2A/PCINT4)PB4) ; also sheet 8
CAP_MISO: D9.13((MISO/PCINT3)PB3) ; also sheet 8
CAP_MOSI: D9.12((MOSI/PCINT2)PB2) ; also sheet 8
CAP_SCLK: D9.11((SCK/PCINT1)PB1) ; also sheet 8
GND: C47.2 C48.1 C49.1 D8.GND D9.22(GND) D9.53(GND1) D9.63(AGND) X20.2 X20.10 ; also sheet 1,2,3,4,5,6,8
N$4: D8.CTS(CTS-I) D8.RTS(RTS-O)
WAKE: D9.19((TOSC1)PG4) ; also sheet 1
XTAL1: B3.1 C48.2 D9.24(XTAL1)
XTAL2: B3.2 C49.2 D9.23(XTAL2)
Unconnected: D9.4((XCK0/AIN0)PE2) D9.8((T3/INT6)PE6) D9.9((CLKO/ICP3/INT7)PE7) D9.17((OC0A/OC1C/PCINT7)PB7) D9.18((TOSC2)PG3) D9.29((ICP1)PD4) D9.30((XCK1)PD5) D9.31((T1)PD6) D9.32((T0)PD7) D9.33((WR)PG0) D9.34((RD)PG1) D9.43((ALE)PG2) X20.7 X20.8

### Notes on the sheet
- Rev 0 | Initial revision
- Rev 3 | PM (BT,AC97,HV)

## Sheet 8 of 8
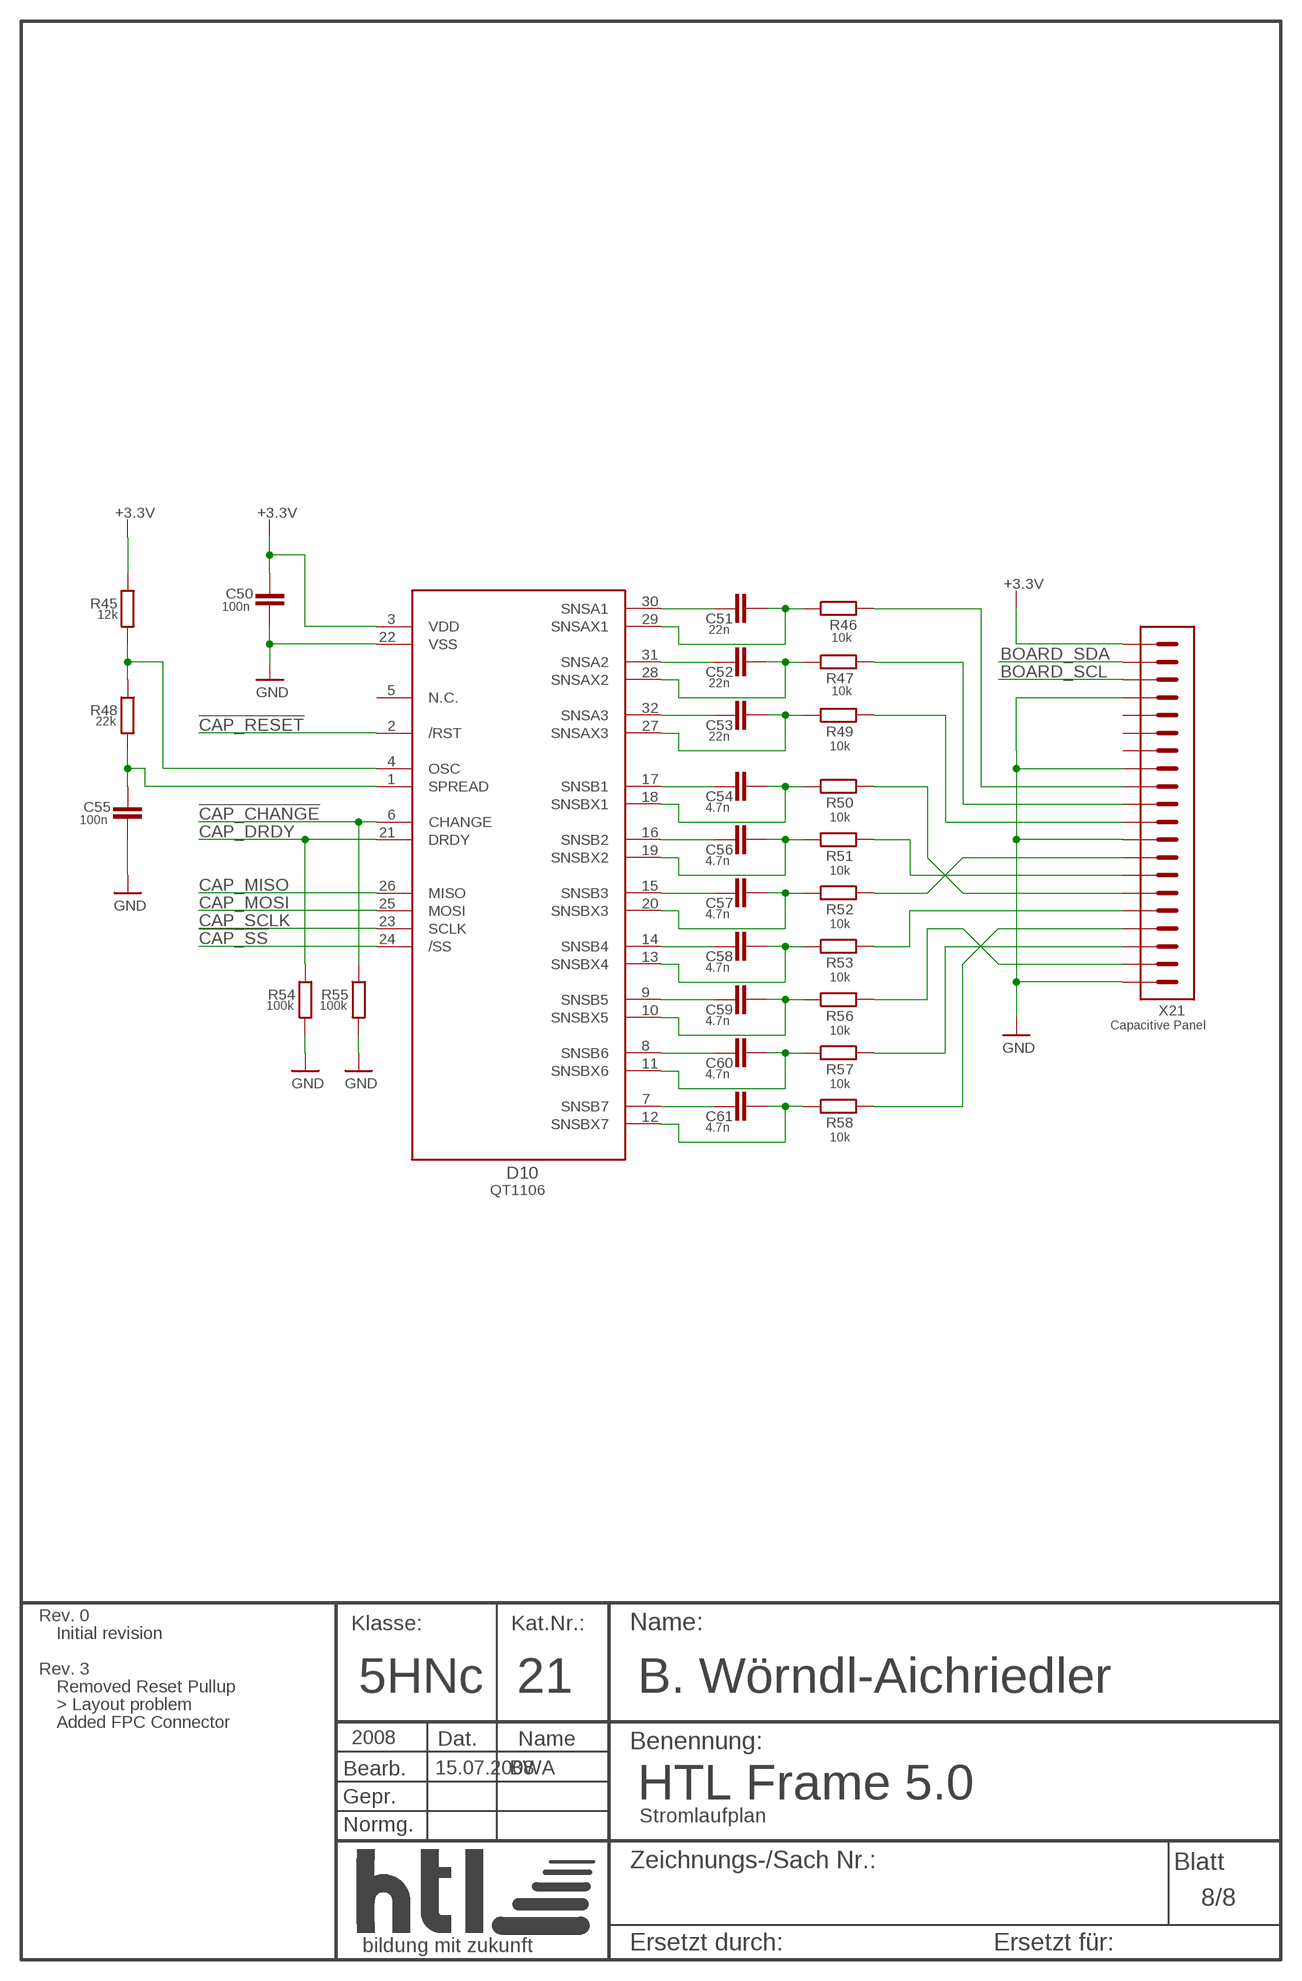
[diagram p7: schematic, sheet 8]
FRAME7 (HTL-FRAME-A4): CAT_NO: 21; CLASS: 5HNc; LAST_EDIT: 15.07.2008; SHORTNAME: BWA; SUBTITLE: Stromlaufplan; TITLE: HTL Frame 5.0; USERNAME: B. Wörndl-Aichriedler; YEAR: 2008

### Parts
C50  100n  C-EUC1206  [C1206]
C51  22n  C-EUC1206  [C1206]
C52  22n  C-EUC1206  [C1206]
C53  22n  C-EUC1206  [C1206]
C54  4.7n  C-EUC1206  [C1206]
C55  100n  C-EUC1206  [C1206]
C56  4.7n  C-EUC1206  [C1206]
C57  4.7n  C-EUC1206  [C1206]
C58  4.7n  C-EUC1206  [C1206]
C59  4.7n  C-EUC1206  [C1206]
C60  4.7n  C-EUC1206  [C1206]
C61  4.7n  C-EUC1206  [C1206]
D10  QT1106  [MLF32]
R45  12k  R-EU_R1206  [R1206]
R46  10k  R-EU_R0805  [R0805]
R47  10k  R-EU_R0805  [R0805]
R48  22k  R-EU_R1206  [R1206]
R49  10k  R-EU_R0805  [R0805]
R50  10k  R-EU_R0805  [R0805]
R51  10k  R-EU_R0805  [R0805]
R52  10k  R-EU_R0805  [R0805]
R53  10k  R-EU_R0805  [R0805]
R54  100k  R-EU_R0805  [R0805]
R55  100k  R-EU_R0805  [R0805]
R56  10k  R-EU_R0805  [R0805]
R57  10k  R-EU_R0805  [R0805]
R58  10k  R-EU_R0805  [R0805]
X21  Capacitive Panel  FPC-20-1MM  [FPC-20-1MM]

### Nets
!CAP_CHANGE: D10.6(CHANGE) R55.1 ; also sheet 7
!CAP_RESET: D10.2(/RST) ; also sheet 7
!CAP_SS: D10.24(/SS) ; also sheet 7
+3.3V: C50.1 D10.3(VDD) R45.1 X21.P$20 ; also sheet 1,2,3,4,5,6,7
BOARD_SCL: X21.P$18 ; also sheet 7
BOARD_SDA: X21.P$19 ; also sheet 7
CAP_DRDY: D10.21(DRDY) R54.1 ; also sheet 7
CAP_MISO: D10.26(MISO) ; also sheet 7
CAP_MOSI: D10.25(MOSI) ; also sheet 7
CAP_SCLK: D10.23(SCLK) ; also sheet 7
GND: C50.2 C55.2 D10.22(VSS) R54.2 R55.2 X21.P$1 X21.P$9 X21.P$13 X21.P$17 ; also sheet 1,2,3,4,5,6,7
N$3: R52.2 X21.P$8
N$36: R46.2 X21.P$12
N$37: R47.2 X21.P$11
N$38: R49.2 X21.P$10
N$39: R50.2 X21.P$6
N$40: C52.1 D10.31(SNSA2)
N$41: C52.2 D10.28(SNSAX2) R47.1
N$42: C51.1 D10.30(SNSA1)
N$43: C51.2 D10.29(SNSAX1) R46.1
N$44: C53.1 D10.32(SNSA3)
N$45: C53.2 D10.27(SNSAX3) R49.1
N$46: C54.1 D10.17(SNSB1)
N$47: C54.2 D10.18(SNSBX1) R50.1
N$48: C56.1 D10.16(SNSB2)
N$49: C56.2 D10.19(SNSBX2) R51.1
N$50: C57.1 D10.15(SNSB3)
N$51: C57.2 D10.20(SNSBX3) R52.1
N$52: C58.1 D10.14(SNSB4)
N$53: C58.2 D10.13(SNSBX4) R53.1
N$54: C59.1 D10.9(SNSB5)
N$55: C59.2 D10.10(SNSBX5) R56.1
N$56: C60.1 D10.8(SNSB6)
N$57: C60.2 D10.11(SNSBX6) R57.1
N$58: C61.1 D10.7(SNSB7)
N$59: C61.2 D10.12(SNSBX7) R58.1
N$60: C55.1 D10.1(SPREAD) R48.2
N$61: D10.4(OSC) R45.2 R48.1
N$62: R51.2 X21.P$7
N$64: R53.2 X21.P$5
N$65: R56.2 X21.P$2
N$66: R57.2 X21.P$3
N$67: R58.2 X21.P$4
Unconnected: D10.5(N.C.) X21.P$14 X21.P$15 X21.P$16

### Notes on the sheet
- Rev. 0
- Initial revision
- Rev. 3
- Removed Reset Pullup
- > Layout problem
- Added FPC Connector

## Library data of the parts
B1 = xmedia:TOTX147
B2 B3 = xmedia:CRYSTAL: CRYSTAL
C1 C3 C6 C9 C17 C20 C24 C27 C36 C45 = xmedia-rcl:CPOL-EU: POLARIZED CAPACITOR, European symbol
C2 C4 C5 C7 C8 C10-C16 C18 C19 C21-C23 C25 C26 C28-C35 C37-C44 C46-C61 = xmedia-rcl:C-EU: CAPACITOR, European symbol
D1 = xmedia:ATTINY45: MICROCONTROLLER 1K ROM 128 bytes RAM 128 bytes EEPROM
D2 = xmedia:74*04: Hex INVERTER
D3 = xmedia:ADV7125
D4 D5 = xmedia:SPANSION_SPI_MEMORY
D6 = xmedia:XG-182M
D7 = xmedia:CS4202
D8 = xmedia:BLUE_SMIRF
D9 = xmedia:ATMEGA2561*: MICROCONTROLLER 256 Kbytes FLASH 4 Kbytes EEPROM 8 Kbytes SRAM 54 General Purpose I/O pins 6-channels 16-bit PWM 2 x Serial USARTs 8-channels 10-bit A/D
D10 = xmedia:QT1106
L1-L3 = xmedia-rcl:L-EU: INDUCTOR, European symbol
N1 N2 = xmedia:78: VOLTAGE REGULATOR
P1-P19 = xmedia:TP
R1-R59 = xmedia-rcl:R-EU_: RESISTOR, European symbol
V1 V2 = xmedia:SCHOTTKY-DIODE: Schottky Diode
V3 = xmedia:VN700: N-CHANNEL MOS FET
X1-X3 = xmedia:MA18-2W: PIN HEADER
X4 = xmedia:M02: AMP QUICK CONNECTOR
X5 = xmedia:MOLEX4
X6 = xmedia:MA03-1: PIN HEADER
X7 = xmedia:ZIF-40
X8 = xmedia:HF15: SUB-D
X9 = xmedia:SD_CARD_SOCKET: SD/MMC Socket Media socket for SD and MMC cards. Push-push type. Schematic element and footprint production proven. Spark Fun Electronics SKU : PRT-00136
X10 X12 X15 X16 = xmedia:1503_03
X11 X13 X14 = xmedia:MA03-2: PIN HEADER
X17 = xmedia:MA08-2: PIN HEADER
X18 = xmedia:FPC-4
X19 = xmedia:MA04-1: PIN HEADER
X20 = xmedia:2510-: 3M (TM) Pak 100 4-Wall Header Source: 3M
X21 = xmedia:FPC-20-1MM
